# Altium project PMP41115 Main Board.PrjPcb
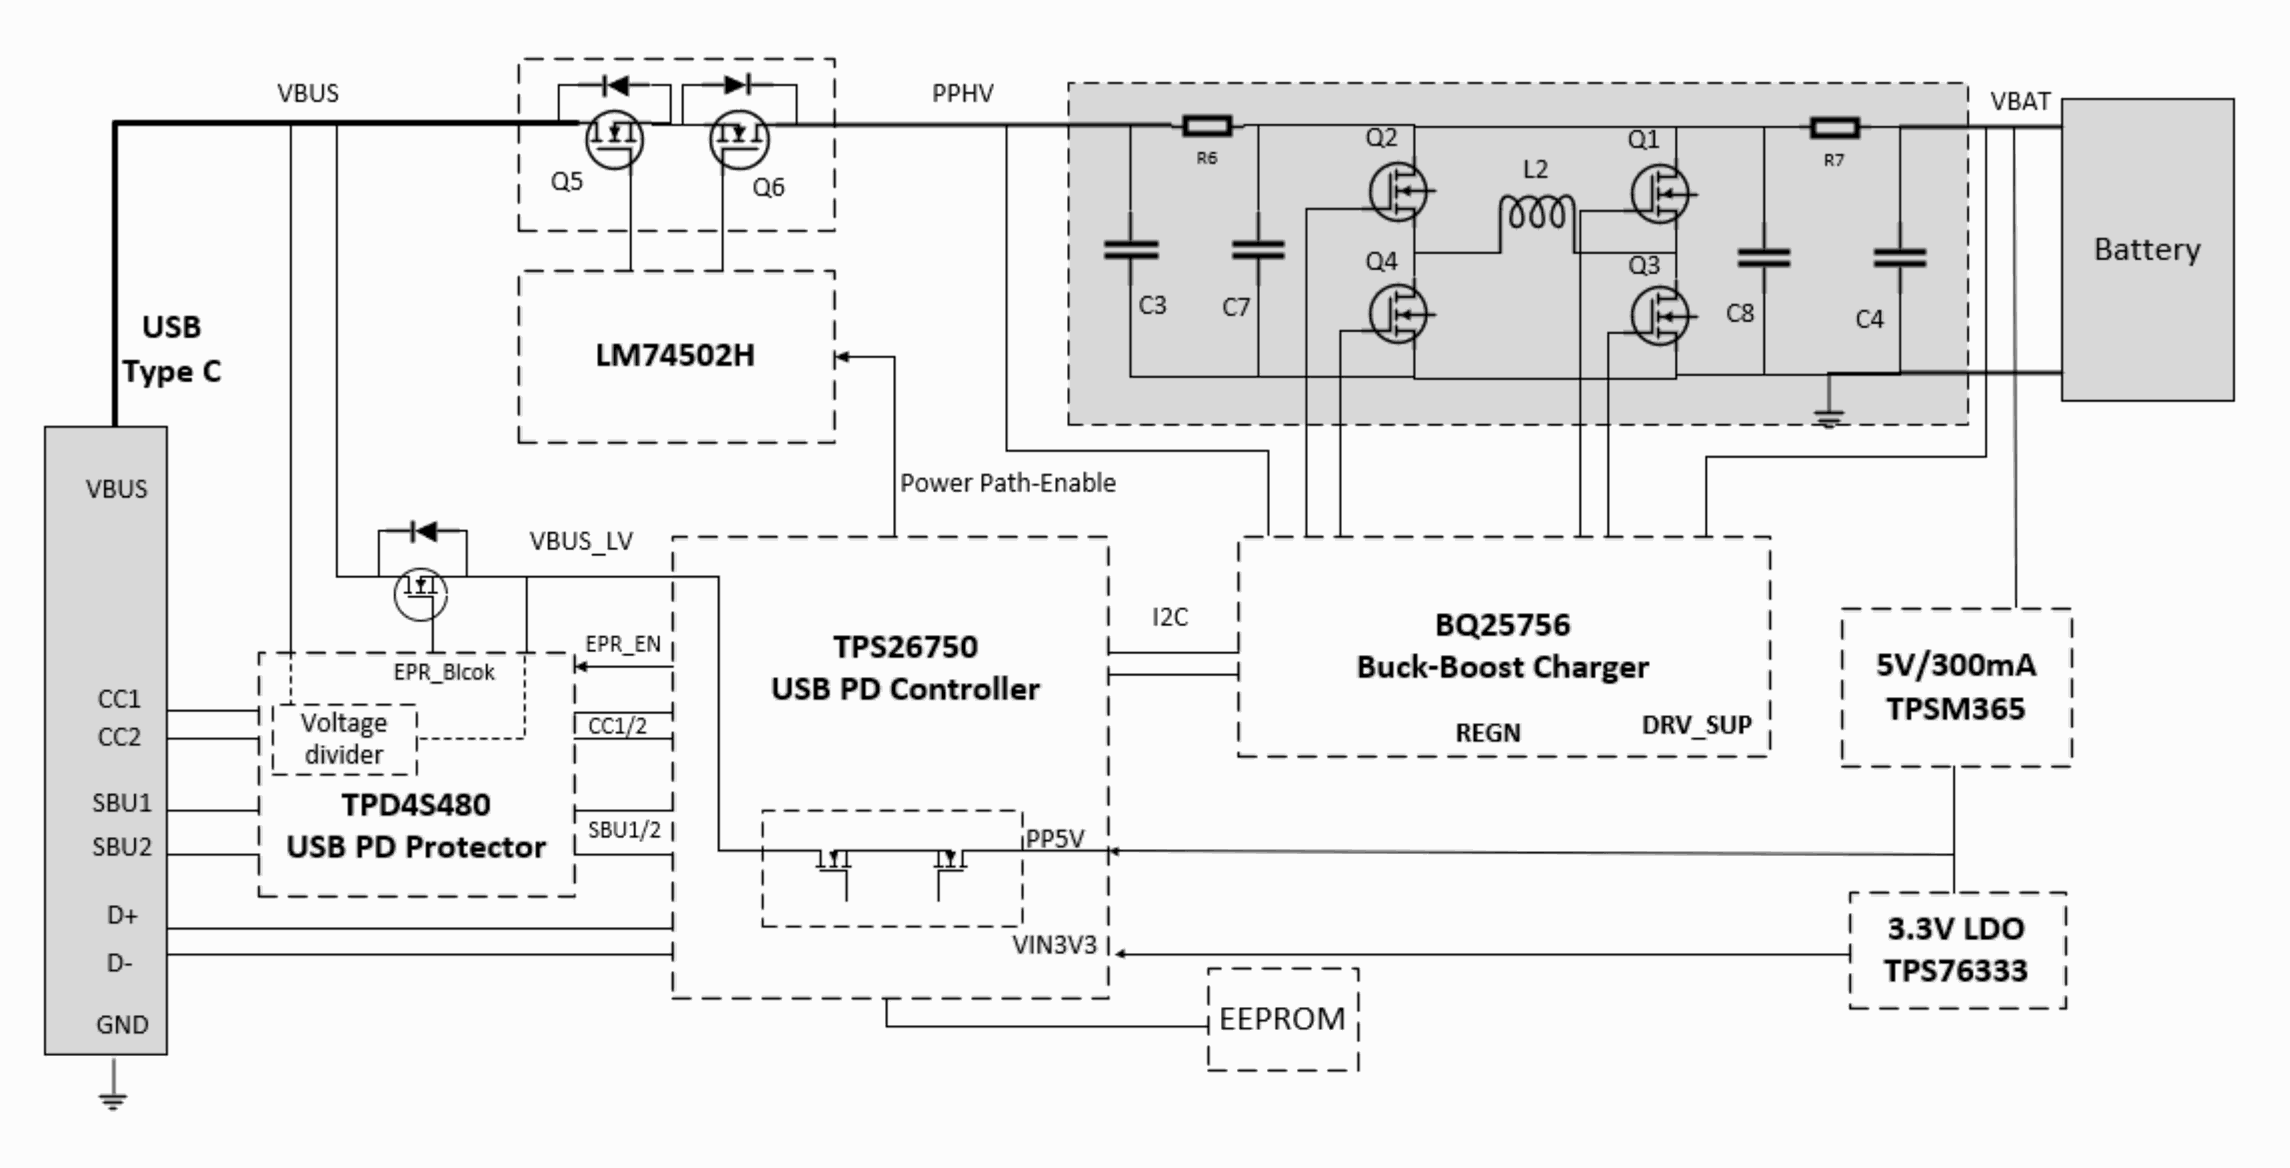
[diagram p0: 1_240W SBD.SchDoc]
CopyrightYear: 2024; PCB_Layout: Max Wang; PRJ_Customer: Public Release; PRJ_Engineer: Max Wang; PRJ_Number: PMP41115; PRJ_Title: 240W USB PD3.1 DCDC Charger; TechSupport: http://www.ti.com/support; TID: N/A
4 sheets, 168 parts. Net scope: flat (ports and power ports of the same name join across sheets).
Board file: PMP41115.PcbDoc
Sheets:
  1_240W SBD.SchDoc
  2_PD Control TPS26750.SchDoc
  4_PP5V Bias.SchDoc
  3_BQ25756 Charger.SchDoc

## Sheet 1_240W SBD.SchDoc
size A2; Date: Not shown in title block; ApprovedBy: Not shown in title block; CheckedBy: Not shown in title block; Author: Not shown in title block; CompanyName: Not shown in title block; Engineer: Not shown in title block; Organization: Not shown in title block; Address1: Not shown in title block; Address2: Not shown in title block; Address3: Not shown in title block; Address4: Not shown in title block; DocumentNumber: 1; Revision: Use project parameter SCH_Rev; SheetNumber: 1; SheetTotal: 1; PageSetup: Record=PageOptions¦CenterHorizontal=True¦CenterVertical=True¦PrintScale=0.69¦XCorrection=1.00¦YCorrection=1.00¦PrintKind=0¦BorderSize=5000000¦LeftOffset=0¦BottomOffset=0¦Orientation=2¦PaperLength=1000¦PaperWidth=1000¦Scale=100¦PaperSource=15¦PrintQuality=600¦MediaType=1¦DitherType=10¦PaperKind=Letter¦PrintScaleMode=1

## Sheet 2_PD Control TPS26750.SchDoc
size A2; Date: Not shown in title block; ApprovedBy: Not shown in title block; CheckedBy: Not shown in title block; Author: Not shown in title block; CompanyName: Not shown in title block; Engineer: Not shown in title block; Organization: Not shown in title block; Address1: Not shown in title block; Address2: Not shown in title block; Address3: Not shown in title block; Address4: Not shown in title block; DocumentNumber: 2; Revision: Use project parameter SCH_Rev; SheetNumber: 2; SheetTotal: 14; PageSetup: Record=PageOptions¦CenterHorizontal=True¦CenterVertical=True¦PrintScale=1.00¦XCorrection=1.00¦YCorrection=1.00¦PrintKind=0¦BorderSize=5000000¦LeftOffset=0¦BottomOffset=0¦Orientation=2¦PaperLength=1000¦PaperWidth=1000¦Scale=100¦PaperSource=15¦PrintQuality=600¦MediaType=1¦DitherType=10¦PaperKind=Letter¦PrintScaleMode=1
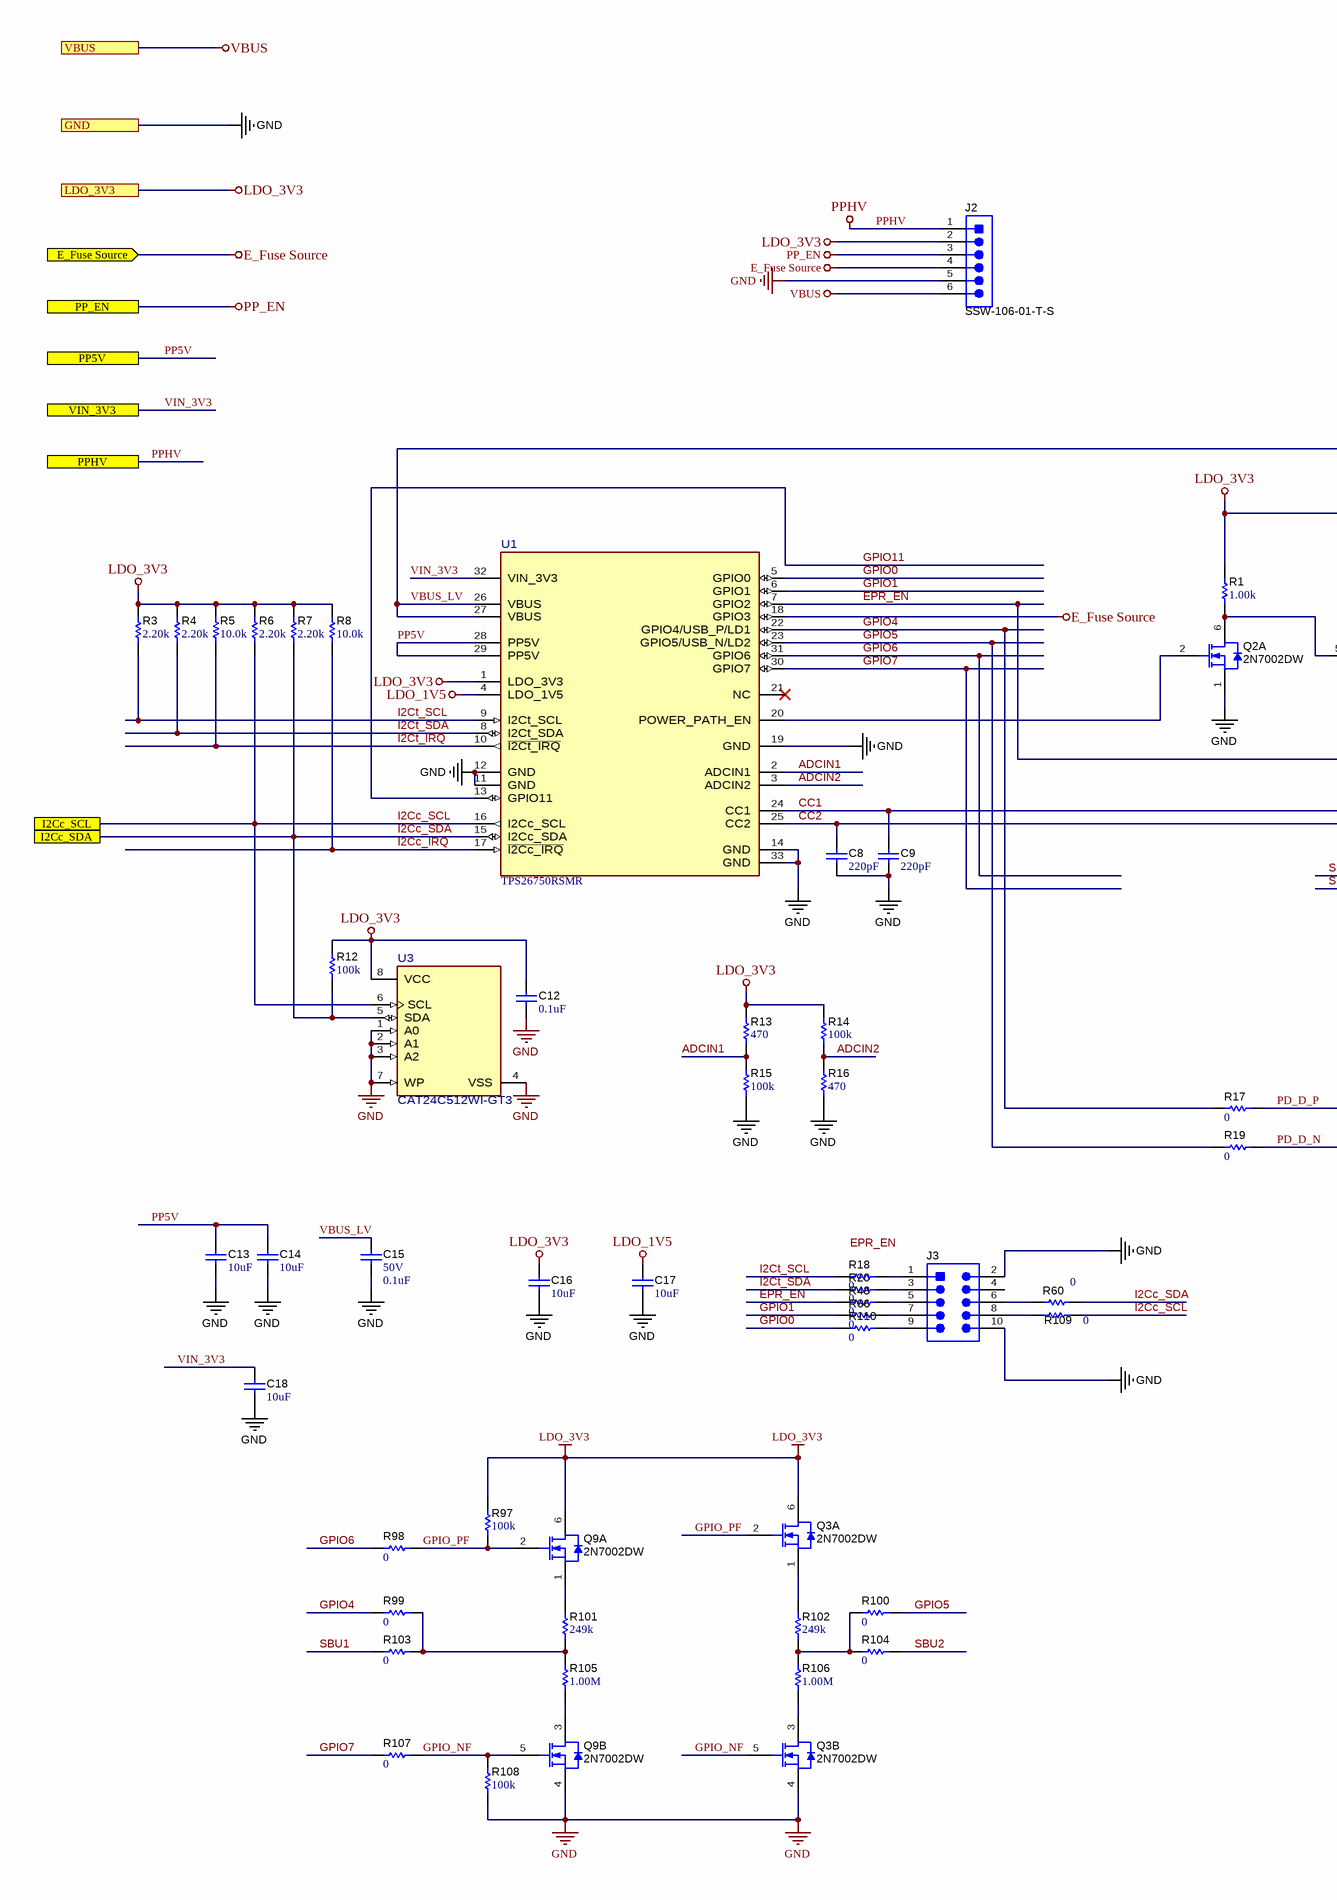
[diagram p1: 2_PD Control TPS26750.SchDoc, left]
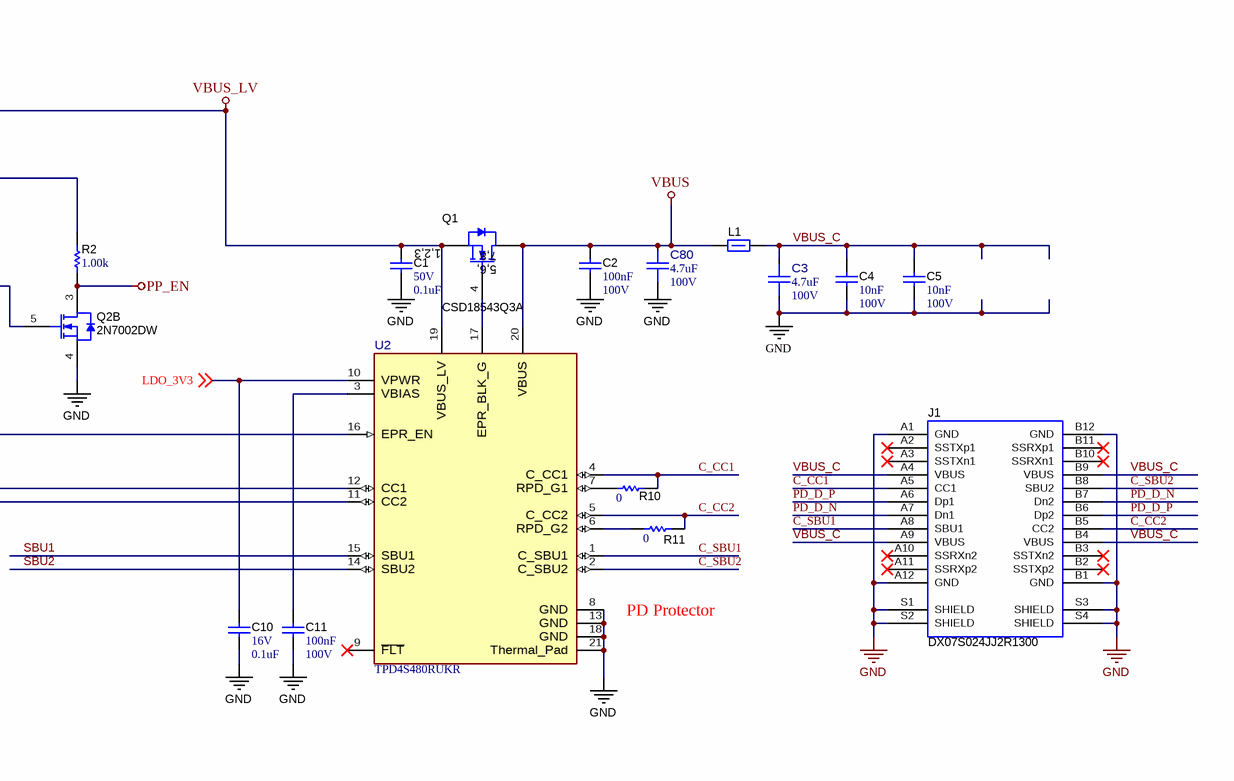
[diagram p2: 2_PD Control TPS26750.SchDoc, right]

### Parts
C1  VDC_V: 50V  ValueDisplayed: 0.1uF  [0402L]  (hidden comment: C1005X5R1H104K050BB)
C2  Cap_F: 100nF  VDC_V: 100V  [0603]  (hidden comment: GRM188R72A104KA35J)
C3  ValueDisplayed: 4.7uF  VDC_V: 100V  [FP-C2012X5R2A475K125AC_0805-MFG]  (hidden comment: C2012X5R2A475K125AC)
C4  Cap_F: 10nF  VDC_V: 100V  [0603L]  (hidden comment: C0603X103K1RACTU)
C5  Cap_F: 10nF  VDC_V: 100V  [0603L]  (hidden comment: C0603X103K1RACTU)
C8  ValueDisplayed: 220pF  [0201_033L]  (hidden comment: CGA1A2X7R1H221K030BA)
C9  ValueDisplayed: 220pF  [0201_033L]  (hidden comment: CGA1A2X7R1H221K030BA)
C10  VDC_V: 16V  ValueDisplayed: 0.1uF  [0402]  (hidden comment: 885012205037)
C11  Cap_F: 100nF  VDC_V: 100V  [0603]  (hidden comment: GRM188R72A104KA35J)
C12  ValueDisplayed: 0.1uF  [0402L]  (hidden comment: CGA2B3X7R1H104K050BB)
C13  ValueDisplayed: 10uF  [0603L]  (hidden comment: GRM188R61E106MA73D)
C14  ValueDisplayed: 10uF  [0603L]  (hidden comment: GRM188R61E106MA73D)
C15  VDC_V: 50V  ValueDisplayed: 0.1uF  [0402L]  (hidden comment: C1005X5R1H104K050BB)
C16  ValueDisplayed: 10uF  [0402_070]  (hidden comment: CL05A106MP5NUNC)
C17  ValueDisplayed: 10uF  [0402_070]  (hidden comment: CL05A106MP5NUNC)
C18  ValueDisplayed: 10uF  [0402_070]  (hidden comment: CL05A106MP5NUNC)
C80  ValueDisplayed: 4.7uF  VDC_V: 100V  [FP-C2012X5R2A475K125AC_0805-MFG]  (hidden comment: C2012X5R2A475K125AC)
J1  DX07S024JJ2R1300  [JAE_DX07S024JJ2R1300]
J2  SSW-106-01-T-S  [Samtec_SSW-106-01-x-S]
J3  PEC05DAAN  [CONN_PEC05DAAN]  (value not drawn)
L1  742792021  [0805L]  (value not drawn)
Q1  CSD18543Q3A  [DNH0008A]
Q2  2N7002DW  [SOT-363]  (parts A,B of 2)
Q3  2N7002DW  [SOT-363]  (parts A,B of 2)
Q9  2N7002DW  [SOT-363]  (parts A,B of 2)
R1  ValueDisplayed: 1.00k  [0402]  (hidden comment: ERJ-2RKF1001X)
R2  ValueDisplayed: 1.00k  [0402]  (hidden comment: ERJ-2RKF1001X)
R3  ValueDisplayed: 2.20k  [0402]  (hidden comment: RC0402FR-072K2L)
R4  ValueDisplayed: 2.20k  [0402]  (hidden comment: RC0402FR-072K2L)
R5  ValueDisplayed: 10.0k  [0402]  (hidden comment: CRCW040210K0DHEDP)
R6  ValueDisplayed: 2.20k  [0402]  (hidden comment: RC0402FR-072K2L)
R7  ValueDisplayed: 2.20k  [0402]  (hidden comment: RC0402FR-072K2L)
R8  ValueDisplayed: 10.0k  [0402]  (hidden comment: CRCW040210K0DHEDP)
R10  ValueDisplayed: 0  [0201L]  (hidden comment: CRCW02010000Z0ED)
R11  ValueDisplayed: 0  [0201L]  (hidden comment: CRCW02010000Z0ED)
R12  ValueDisplayed: 100k  [0201L]  (hidden comment: RC0201FS-7D100KL)
R13  ValueDisplayed: 470  [0603]  (hidden comment: RT0603BRD07470RL)
R14  ValueDisplayed: 100k  [0603L]  (hidden comment: RC0603FR-07100KL)
R15  ValueDisplayed: 100k  [0603L]  (hidden comment: RC0603FR-07100KL)
R16  ValueDisplayed: 470  [0603]  (hidden comment: RT0603BRD07470RL)
R17  ValueDisplayed: 0  [0201L]  (hidden comment: CRCW02010000Z0ED)
R18  ValueDisplayed: 0  [0402]  (hidden comment: RC0402JR-070RL)
R19  ValueDisplayed: 0  [0201L]  (hidden comment: CRCW02010000Z0ED)
R20  ValueDisplayed: 0  [0402]  (hidden comment: RC0402JR-070RL)
R48  ValueDisplayed: 0  [0402]  (hidden comment: RC0402JR-070RL)
R60  ValueDisplayed: 0  [0402]  (hidden comment: RC0402JR-070RL)
R66  ValueDisplayed: 0  [0402]  (hidden comment: RC0402JR-070RL)
R97  ValueDisplayed: 100k  [0402L]  (hidden comment: RC1005F104CS)
R98  ValueDisplayed: 0  [0402]  (hidden comment: RC0402JR-070RL)
R99  ValueDisplayed: 0  [0402]  (hidden comment: RC0402JR-070RL)
R100  ValueDisplayed: 0  [0402]  (hidden comment: RC0402JR-070RL)
R101  ValueDisplayed: 249k  [0603]  (hidden comment: RG1608P-2493-B-T5)
R102  ValueDisplayed: 249k  [0603]  (hidden comment: RG1608P-2493-B-T5)
R103  ValueDisplayed: 0  [0402]  (hidden comment: RC0402JR-070RL)
R104  ValueDisplayed: 0  [0402]  (hidden comment: RC0402JR-070RL)
R105  ValueDisplayed: 1.00M  [0402L]  (hidden comment: ERJ-2RKF1004X)
R106  ValueDisplayed: 1.00M  [0402L]  (hidden comment: ERJ-2RKF1004X)
R107  ValueDisplayed: 0  [0402]  (hidden comment: RC0402JR-070RL)
R108  ValueDisplayed: 100k  [0402L]  (hidden comment: RC1005F104CS)
R109  ValueDisplayed: 0  [0402]  (hidden comment: RC0402JR-070RL)
R110  ValueDisplayed: 0  [0402]  (hidden comment: RC0402JR-070RL)
U1  TPS26750RSMR  [RSM0032B-MFG]
U2  TPD4S480RUKR  [RUK0020B-MFG]
U3  CAT24C512WI-GT3  [FP-CAT24C512WI-GT3_SOIC8-IPC_C]

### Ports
E_Fuse Source (in), GND, I2Cc_SCL, I2Cc_SDA, LDO_3V3, PP5V, PP_EN, PPHV, VBUS, VIN_3V3

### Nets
E_Fuse Source: J2.4 U1.18(GPIO3) ; port E_Fuse Source
GND: C1.2 C2.2 C3.1 C4.2 C5.2 C8.2 C9.2 C10.2 C11.1 C12.2 C13.2 C14.2 C15.2 C16.1 C17.1 C18.2 C80.1 J1.A1(GND) J1.A12(GND) J1.B1(GND) J1.B12(GND) J1.S1(SHIELD) J1.S2(SHIELD) J1.S3(SHIELD) J1.S4(SHIELD) J2.5 J3.2 J3.10 Q2.1(S) Q2.4(S) Q3.4(S) Q9.4(S) R15.1 R16.1 R108.1 U1.11(GND) U1.12(GND) U1.14(GND) U1.19(GND) U1.33(GND) U2.8(GND) U2.13(GND) U2.18(GND) U2.21(Thermal_Pad) U3.1(A0) U3.2(A1) U3.3(A2) U3.4(VSS) U3.7(WP) ; port GND
LDO_1V5: C17.2 U1.4(LDO_1V5)
LDO_3V3: C10.1 C12.1 C16.2 J2.2 Q3.6(D) Q9.6(D) R1.2 R2.2 R3.2 R4.2 R5.2 R6.2 R7.2 R8.2 R12.2 R13.2 R14.2 R97.2 U1.1(LDO_3V3) U2.10(VPWR) U3.8(VCC) ; off-sheet LDO_3V3, port LDO_3V3
PP_EN: J2.3 Q2.3(D) R2.1 ; port PP_EN
PPHV: J2.1 ; port PPHV
VBUS: C2.1 C80.2 J2.6 L1.1 Q1.5(D) Q1.6(D) Q1.7(D) Q1.8(D) Q1.9(D) U2.20(VBUS) ; port VBUS
VBUS_LV: C1.1 C15.1 Q1.1(S) Q1.2(S) Q1.3(S) U1.26(VBUS) U1.27(VBUS) U2.19(VBUS_LV)
VIN_3V3: C18.1 U1.32(VIN_3V3) ; port VIN_3V3
ADCIN1: R13.1 R15.2 U1.2(ADCIN1)
ADCIN2: R14.1 R16.2 U1.3(ADCIN2)
C_CC1: J1.A5(CC1) R10.2 U2.4(C_CC1)
C_CC2: J1.B5(CC2) R11.2 U2.5(C_CC2)
C_SBU1: J1.A8(SBU1) U2.1(C_SBU1)
C_SBU2: J1.B8(SBU2) U2.2(C_SBU2)
CC1: C9.1 U1.24(CC1) U2.12(CC1)
CC2: C8.1 U1.25(CC2) U2.11(CC2)
EPR_EN: R48.1 U1.7(GPIO2) U2.16(EPR_EN)
GPIO0: R110.1 U1.5(GPIO0)
GPIO1: R66.1 U1.6(GPIO1)
GPIO4: R17.1 R99.1 U1.22(GPIO4/USB_P/LD1)
GPIO5: R19.1 R100.2 U1.23(GPIO5/USB_N/LD2)
GPIO6: R98.1 U1.31(GPIO6)
GPIO7: R107.1 U1.30(GPIO7)
GPIO11: U1.13(GPIO11)
GPIO_NF: Q3.5(G) Q9.5(G) R107.2 R108.2
GPIO_PF: Q3.2(G) Q9.2(G) R97.1 R98.2
I2Cc_SCL: R6.1 R109.2 U1.16(I2Cc_SCL) U3.6(SCL) ; port I2Cc_SCL
I2Cc_SDA: R7.1 R12.1 R60.2 U1.15(I2Cc_SDA) U3.5(SDA) ; port I2Cc_SDA
I2Ct_SCL: R3.1 R18.1 U1.9(I2Ct_SCL)
I2Ct_SDA: R4.1 R20.1 U1.8(I2Ct_SDA)
~{I2Cc_IRQ}: R8.1 U1.17(~{I2Cc_IRQ})
~{I2Ct_IRQ}: R5.1 U1.10(~{I2Ct_IRQ})
PD_D_N: J1.A7(Dn1) J1.B7(Dn2) R19.2
PD_D_P: J1.A6(Dp1) J1.B6(Dp2) R17.2
PP5V: C13.1 C14.1 U1.28(PP5V) U1.29(PP5V) ; port PP5V
SBU1: R103.1 U2.15(SBU1)
SBU2: R104.2 U2.14(SBU2)
VBUS_C: C3.2 C4.1 C5.1 J1.A4(VBUS) J1.A9(VBUS) J1.B4(VBUS) J1.B9(VBUS) L1.2
NetC11_2: C11.2 U2.3(VBIAS)
NetJ3_1: J3.1 R18.2
NetJ3_3: J3.3 R20.2
NetJ3_5: J3.5 R48.2
NetJ3_6: J3.6 R60.1
NetJ3_7: J3.7 R66.2
NetJ3_8: J3.8 R109.1
NetJ3_9: J3.9 R110.2
NetQ1_4: Q1.4(G) U2.17(EPR_BLK_G)
NetQ2_2: Q2.2(G) U1.20(POWER_PATH_EN)
NetQ2_5: Q2.5(G) Q2.6(D) R1.1
NetQ3_1: Q3.1(S) R102.2
NetQ3_3: Q3.3(D) R106.1
NetQ9_1: Q9.1(S) R101.2
NetQ9_3: Q9.3(D) R105.1
NetR10_1: R10.1 U2.7(RPD_G1)
NetR11_1: R11.1 U2.6(RPD_G2)
NetR99_2: R99.2 R101.1 R103.2 R105.2
NetR100_1: R100.1 R102.1 R104.1 R106.2

Not connected (* = marked no-connect by the designer): J1 A2(SSTXp1)* A3(SSTXn1)* A10(SSRXn2)* A11(SSRXp2)* B2(SSTXp2)* B3(SSTXn2)* B10(SSRXn1)* B11(SSRXp1)*; J3 4; U1 21(NC)*; U2 9(~{FLT})*

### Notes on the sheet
- (near U2) PD Protector
- Labels drawn without touching a wire or pin: EPR_EN

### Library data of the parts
C1 C15 = CMP-0006279-2: CAP, CERM, 0.1 uF, 50 V, +/- 10%, X5R, 0402; Manufacturer: TDK; TaMin_C: -55°C; ESR_ohm: 39.064m; Polarized: N; SizeAreaWB_mm2: 3; Value1: 0.039064 ohm; U/M: EA; Value: 0.1uF; TaMax_C: 85°C; SizeZ_mm: 0.6; SizeX_mm: 1; SizeY_mm: 0.5; Cap_Case: 0402; Cap_F: 100nF; IRMS_A: 814.669mA; AEC Category: Q200
C2 C11 = CMP-0007470-4: CAP, CERM, 0.1 uF, 100 V, +/- 10%, X7R, 0603; Manufacturer: MuRata; TaMin_C: -55°C; Polarized: N; SizeAreaWB_mm2: 4.68; Value1: Unknown; U/M: EA; Value: 0.1uF; TaMax_C: 125°C; SizeZ_mm: 1; SizeX_mm: 1.6; SizeY_mm: 0.8; SizeArea_mm2: 1.28; AEC Category: Q200
C3 C80 = CMP-0098058-1: 4.7 µF ±10% 100V Ceramic Capacitor X5R 0805 (2012 Metric); Manufacturer: TDK; AEC Qualified: No; SizeZ_mm: 1.5mm; Value: 4.7µF; TempCo: 15%
C4 C5 = CMP-0006977-4: CAP, CERM, 0.01 uF, 100 V, +/- 10%, X7R, 0603; Manufacturer: Kemet; TaMin_C: -55°C; Polarized: N; SizeAreaWB_mm2: 4.68; Value1: Unknown; U/M: EA; Value: 0.01uF; TaMax_C: 125°C; SizeZ_mm: 1; SizeX_mm: 1.6; SizeY_mm: 0.8; Cap_Case: 0603; SizeArea_mm2: 1.28; AEC Category: Q200
C8 C9 = CMP-0009652-3: CAP, CERM, 220 pF, 50 V, +/- 10%, X7R, AEC-Q200 Grade 1, 0201; Manufacturer: TDK; TaMin_C: -55°C; ESR_ohm: 11.6275; Polarized: N; SizeAreaWB_mm2: 2.08; Value1: 11.6275 ohm; U/M: EA; Value: 220pF; TaMax_C: 125°C; SizeZ_mm: 0.33; SizeX_mm: 0.6; SizeY_mm: 0.3; Cap_Case: 0201_033; Value2: 50V; SizeArea_mm2: 0.18; AEC Qualified: Y; IRMS_A: 200.785mA; AEC Grade: 1; AEC Category: Q200
C10 = CMP-0006228-1: CAP, CERM, 0.1 uF, 16 V, +/- 10%, X7R, 0402; Manufacturer: Wurth Elektronik; TaMin_C: -55°C; Polarized: N; SizeAreaWB_mm2: 3; Value1: Unknown; U/M: EA; Value: 0.1uF; TaMax_C: 125°C; SizeZ_mm: 0.6; SizeX_mm: 1; SizeY_mm: 0.5; Cap_F: 100nF; AEC Category: Q200
C12 = CMP-0006325-2: CAP, CERM, 0.1 uF, 50 V, +/- 10%, X7R, AEC-Q200 Grade 1, 0402; Manufacturer: TDK; TaMin_C: -55°C; ESR_ohm: 39.064m; Polarized: N; SizeAreaWB_mm2: 3; Value1: 0.039064 ohm; U/M: EA; Value: 0.1uF; TaMax_C: 125°C; SizeZ_mm: 0.6; SizeX_mm: 1; SizeY_mm: 0.5; Cap_Case: 0402; Value2: 50V; AEC Qualified: Y; Cap_F: 100nF; IRMS_A: 814.669mA; AEC Category: Q200
C13 C14 = CMP-0007344-5: CAP, CERM, 10 uF, 25 V, +/- 20%, X5R, 0603; Manufacturer: MuRata; TaMin_C: -55°C; Polarized: N; SizeAreaWB_mm2: 4.68; Value1: Unknown; U/M: EA; Value: 10uF; TaMax_C: 85°C; SizeZ_mm: 1; SizeX_mm: 1.6; SizeY_mm: 0.8; Cap_Case: 0603; Value2: 25V; SizeArea_mm2: 1.28; Cap_F: 10µF; AEC Category: Q200
C16-C18 = CMP-0006339-4: CAP, CERM, 10 uF, 10 V, +/- 20%, X5R, 0402; Manufacturer: Samsung Electro-Mechanics; TaMin_C: -55°C; Polarized: N; SizeAreaWB_mm2: 3; Value1: Unknown; U/M: EA; Value: 10uF; TaMax_C: 85°C; SizeZ_mm: 0.6; SizeX_mm: 1; SizeY_mm: 0.5; Cap_Case: 0402; Value2: 10V; Cap_F: 10µF; AEC Category: Q200
J1 = CMP-0085712-2: Receptacle, USB 3.1 Type C, R/A, Gold, SMT; Manufacturer: JAE Electronics; Current_A: 1.25A; Gender: Female; Voltage_V: 20V; Pitch_mm: 0.5; Row_Count: 2
J2 = CMP-0075621-1: Receptacle, 6x1, 2.54mm, Tin, TH; Manufacturer: Samtec; Pitch_mm: 2.54; Gender: Female; Cert_CSA: Y; Current_A: 5.7A; CT: False; Row_Count: 1
J3 = CMP-0054550-2: Header, 100mil, 5x2, Tin, TH; Manufacturer: Sullins Connector Solutions; Current_A: 3A; Green_Lifecycle: Active; Shrouded: N; Gender: Male; Green_REACh: Passed; Voltage_V: 1.8kV; Row_Count: 2; RowSpacing_mm: 2.54; Cert_UL: Y
L1 = CMP-0003072-1: Ferrite Bead, 22 ohm @ 100 MHz, 6 A, 0805; Manufacturer: Wurth Elektronik; Ztyp@1GHz_Ohm: 40.219; ZTyp@100MHz_Ohm: 22; SizeAreaWB_mm2: 6.75; DCR_ohm: 8m; Value1: 0.008 ohm; Value: 22 ohm; Imax_A: 6A; SizeZ_mm: 1.45; SizeX_mm: 2; SizeY_mm: 1.25; SizeArea_mm2: 2.5
Q1 = CMP-0000826-2: MOSFET, N-CH, 60 V, 35 A, DNH0008A (VSONP-8); Alternate Manufacturer: None; Manufacturer: Texas Instruments; SizeZ_mm: 0.9; ChType: N; Value2: 11.1 nC; Value1: 0.01; VdsMax_V: 60V; SizeX_mm: 3.3; SizeAreaWB_mm2: 18.49; Vgs_V: 20V; QgTyp_nC: 11.1; Value: 60V; Rdson45_ohm: 12m; SizeArea_mm2: 10.89; AEC Category: Q101; IdsMax_A: 35A; ChMode: Enhancement
Q2 Q3 Q9 = CMP-0000770-1: MOSFET, 2-CH, N-CH, 60 V, 0.115 A, SOT-363; Alternate Manufacturer: None; Manufacturer: Fairchild Semiconductor; SizeZ_mm: 1.1; ChType: N; VdsMax_V: 60V; SizeX_mm: 2.2; Vgs_V: 20V; Value: 60V; SizeArea_mm2: 4.84; AEC Category: Q101; IdsMax_A: 115mA; SizeAreaWB_mm2: 10.24; U/M: EA
R1 R2 = CMP-0026657-1: RES, 1.00 k, 1%, 0.1 W, 0402; Manufacturer: Panasonic; Power_W: 100mW; TempCo: 100 ppm/C; Value_Code: 1k00; U/M: EA; Value: 1.00k; EIA_Code: E96; Res_ohm: 1k; SizeX_mm: 1; SizeY_mm: 0.5; SizeZ_mm: 0.6; Value2: 0.1W; VDC_V: 50V; AEC Category: Q200
R3 R4 R6 R7 = CMP-0026729-1: RES, 2.20 k, 1%, 0.063 W, 0402; Manufacturer: Yageo America; Power_W: 63mW; TempCo: 100 ppm/C; Value_Code: 2k20; U/M: EA; Value: 2.20k; Res_ohm: 2.2k; SizeX_mm: 1; SizeY_mm: 0.5; SizeZ_mm: 0.6; Value2: 0.063W; AEC Qualified: N; AEC Category: Q200
R5 R8 = CMP-0026769-1: RES, 10.0 k, 0.5%, 0.063 W, 0402; Manufacturer: Vishay-Dale; Power_W: 63mW; TempCo: 50 ppm/C; Value_Code: 10k0; U/M: EA; Value: 10.0k; EIA_Code: E192; Res_ohm: 10k; SizeX_mm: 1; SizeY_mm: 0.5; SizeZ_mm: 0.6; Value2: 0.063W; VDC_V: 50V; AEC Category: Q200
R10 R11 R17 R19 = CMP-0027008-4: RES, 0, 5%, 0.05 W, 0201; Manufacturer: Vishay-Dale; Power_W: 50mW; TempCo: ppm/C; Value_Code: 0000; Value: 0; EIA_Code: E24; SizeX_mm: 0.6; SizeY_mm: 0.3; SizeZ_mm: 0.26; Value2: 0.05W; SizeArea_mm2: 0.18; AEC Qualified: N; AEC Category: Q200
R12 = CMP-0028069-1: RES, 100 k, 1%, 0.05 W, 0201; Manufacturer: Yageo America; Power_W: 50mW; TempCo: 200 ppm/C; U/M: EA; Value: 100k; EIA_Code: E96; SizeX_mm: 0.6; SizeY_mm: 0.3; SizeZ_mm: 0.26; Value2: 0.05W; SizeArea_mm2: 0.18; AEC Qualified: N; VDC_V: 25V; AEC Category: Q200
R13 R16 = CMP-0024263-1: RES, 470, 0.1%, 0.1 W, 0603; Manufacturer: Yageo America; Power_W: 100mW; TempCo: 25 ppm/C; Value_Code: 470R; U/M: EA; Value: 470; EIA_Code: E192; SizeX_mm: 1.6; SizeY_mm: 0.8; SizeZ_mm: 1; Value2: 0.1W; SizeArea_mm2: 1.28; VDC_V: 75V; AEC Category: Q200
R14 R15 = CMP-0022735-5: RES, 100 k, 1%, 0.1 W, 0603; Manufacturer: Yageo; Power_W: 100mW; TempCo: 100 ppm/C; Value: 100k; EIA_Code: E96; SizeX_mm: 1.6; SizeY_mm: 0.8; SizeZ_mm: 1; Value2: 0.1W; SizeArea_mm2: 1.28; AEC Qualified: N; VDC_V: 75V; AEC Category: Q200; SizeAreaWB_mm2: 4.68
R18 R20 R48 R60 R66 R98-R100 R103 R104 R107 R109 R110 = CMP-0027004-1: RES, 0, 5%, 0.063 W, 0402; Manufacturer: Yageo America; Power_W: 63mW; TempCo: 200 ppm/C; Value_Code: 0000; U/M: EA; Value: 0; EIA_Code: E24; SizeX_mm: 1; SizeY_mm: 0.5; SizeZ_mm: 0.6; Value2: 0.063W; VDC_V: 50V; AEC Category: Q200
R97 R108 = CMP-0026745-1: RES, 100 k, 1%, 0.063 W, 0402; Manufacturer: Samsung Electro-Mechanics; Power_W: 63mW; TempCo: 100 ppm/C; U/M: EA; Value: 100k; EIA_Code: E96; SizeX_mm: 1; SizeY_mm: 0.5; SizeZ_mm: 0.6; Value2: 0.063W; AEC Qualified: N; VDC_V: 80V; AEC Category: Q200
R101 R102 = CMP-0023490-1: RES, 249 k, 0.1%, 0.1 W, 0603; Manufacturer: Susumu Co Ltd; Power_W: 100mW; TempCo: 25 ppm/C; U/M: EA; Value: 249k; EIA_Code: E192; SizeX_mm: 1.6; SizeY_mm: 0.8; SizeZ_mm: 1; Value2: 0.1W; SizeArea_mm2: 1.28; VDC_V: 75V; AEC Category: Q200
R105 R106 = CMP-0026660-1: RES, 1.00 M, 1%, 0.1 W, 0402; Manufacturer: Panasonic; Power_W: 100mW; TempCo: 100 ppm/C; Value_Code: 1M00; U/M: EA; Value: 1.00Meg; EIA_Code: E96; Res_ohm: 1M; SizeX_mm: 1; SizeY_mm: 0.5; SizeZ_mm: 0.6; Value2: 0.1W; VDC_V: 50V; AEC Category: Q200
U1 = CMP-0121143-2: USB Type-C® and USB PD Controller with Integrated Power Switches Optimized for Power Applications; Manufacturer: Texas Instruments; SizeZ_mm: 1mm; AEC Qualified: No; Interface: I2C,USB; Max Supply Voltage: 22V; Min Supply Voltage: 3V; Nominal Supply Current: 1-3mA; Number Of Ports: 1; Standoff Height: 0mm; TaMax_C: +85°C; TaMin_C: -40°C; TJmax_C: +125°C; Usb Standard: USB 3.1; AEC Category: Q200; CompType: IC
U2 = CMP-0034161-1: USB Type-C® 48V EPR Port Protector: Short-to-VBUS Overvoltage and IEC ESD Protection; Manufacturer: Texas Instruments; SizeZ_mm: 0.8mm; AEC Qualified: No; Direction: Bidirectional; Number Of Channels: 4; Operating Supply Voltage: 3.3V; Standoff Height: 0mm; TJmax_C: +125°C
U3 = CMP-0091847-1: EEPROM Memory IC 512Kb (64K x 8) I²C 1MHz 900ns 8-SOIC; Manufacturer: ON Semi; Standoff Height: 0.1mm; AEC Qualified: No; Max Supply Voltage: 5.5V; Interface: I2C; SizeZ_mm: 1.75mm; Memory Size: 512Kbits; Min Supply Voltage: 1.8V

## Sheet 4_PP5V Bias.SchDoc
size A2; Date: Not shown in title block; ApprovedBy: Not shown in title block; CheckedBy: Not shown in title block; Author: Not shown in title block; CompanyName: Not shown in title block; Engineer: Not shown in title block; Organization: Not shown in title block; Address1: Not shown in title block; Address2: Not shown in title block; Address3: Not shown in title block; Address4: Not shown in title block; DocumentNumber: 1; Revision: Use project parameter SCH_Rev; SheetNumber: 1; SheetTotal: 1; PageSetup: Record=PageOptions¦CenterHorizontal=True¦CenterVertical=True¦PrintScale=0.69¦XCorrection=1.00¦YCorrection=1.00¦PrintKind=0¦BorderSize=5000000¦LeftOffset=0¦BottomOffset=0¦Orientation=2¦PaperLength=1000¦PaperWidth=1000¦Scale=100¦PaperSource=15¦PrintQuality=600¦MediaType=1¦DitherType=10¦PaperKind=Letter¦PrintScaleMode=1
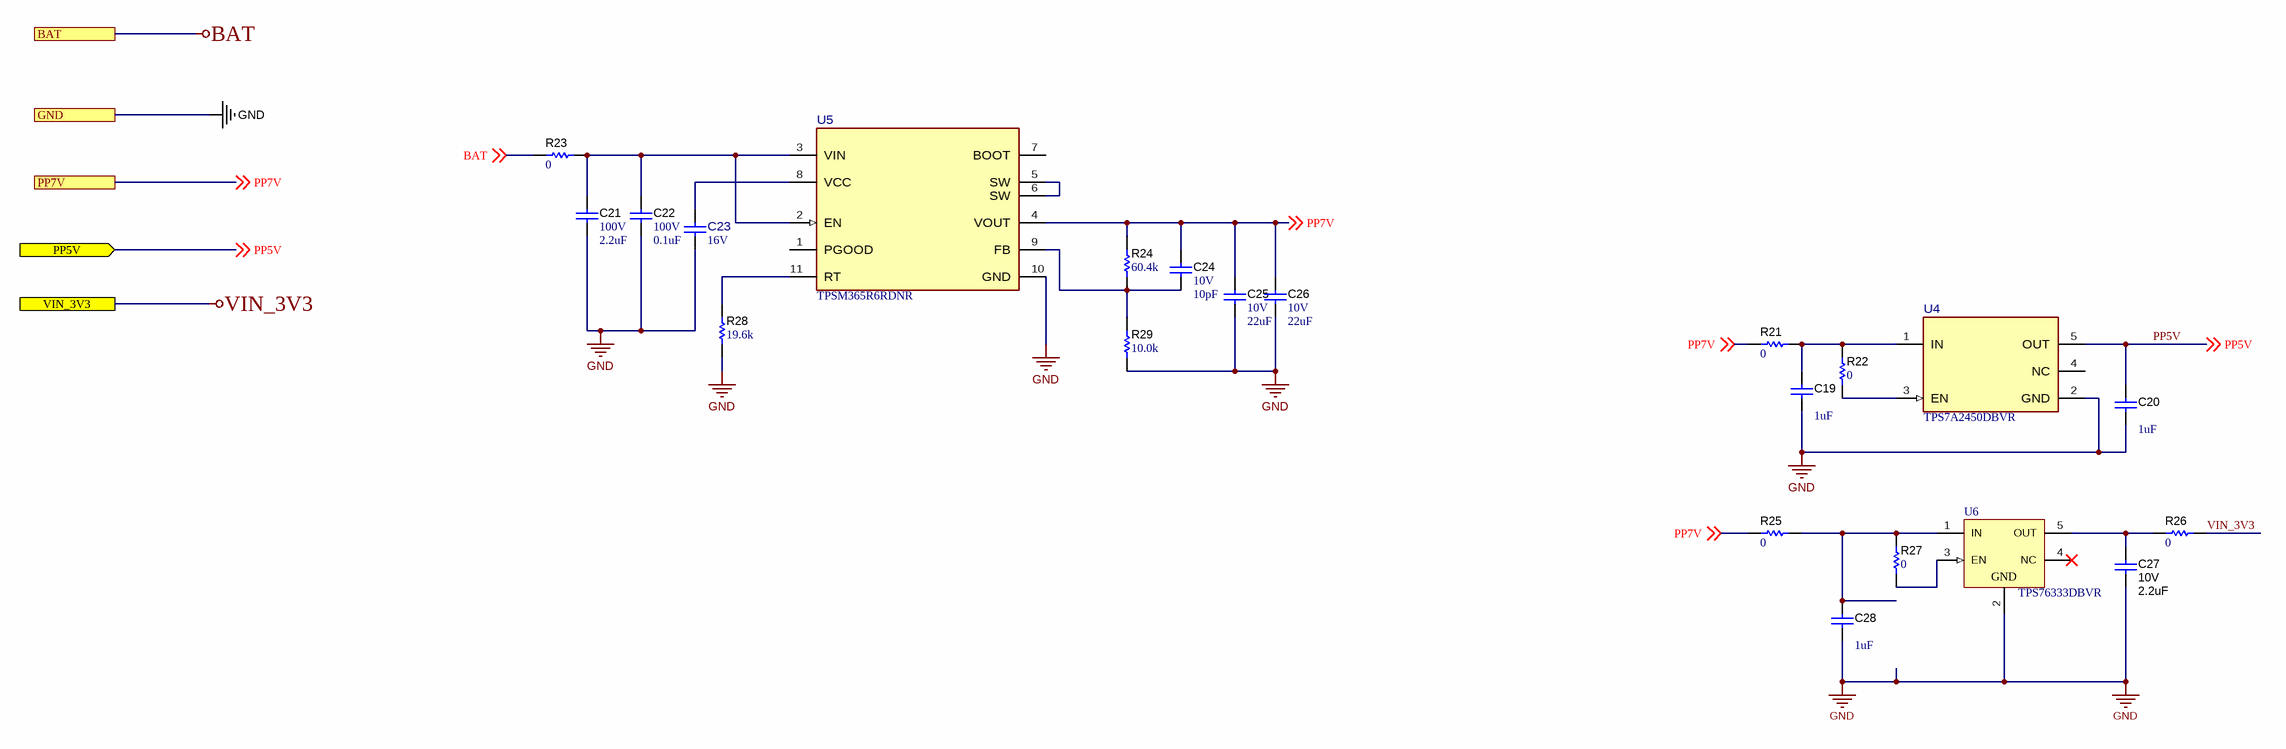
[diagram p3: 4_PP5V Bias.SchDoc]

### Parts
C19  ValueDisplayed: 1uF  [0805_HV]  (hidden comment: C2012X7S2A105K125AB)
C20  ValueDisplayed: 1uF  [0805_HV]  (hidden comment: C2012X7S2A105K125AB)
C21  VDC_V: 100V  ValueDisplayed: 2.2uF  [1206_180]  (hidden comment: C3216X7S2A225K160AB)
C22  VDC_V: 100V  ValueDisplayed: 0.1uF  [0402]  (hidden comment: GRM155R62A104KE14D)
C23  VDC_V: 16V  [FP-0402YD105KAT2A_0402-IPC_B]  (hidden comment: 0402YD105KAT2A)
C24  VDC_V: 10V  ValueDisplayed: 10pF  [0402]  (hidden comment: C0402C100C8GACTU)
C25  VDC_V: 10V  ValueDisplayed: 22uF  [0603]  (hidden comment: CL10A226MP8NUNE)
C26  VDC_V: 10V  ValueDisplayed: 22uF  [0603]  (hidden comment: CL10A226MP8NUNE)
C27  VDC_V: 10V  ValueDisplayed: 2.2uF  [0603]  (hidden comment: CGA3E3X5R1A225K080AB)
C28  ValueDisplayed: 1uF  [0805_HV]  (hidden comment: C2012X7S2A105K125AB)
R21  ValueDisplayed: 0  [0603]  (hidden comment: RC0603JR-070RL)
R22  ValueDisplayed: 0  [0402]  (hidden comment: CMP-0027004-2)
R23  ValueDisplayed: 0  [0402]  (hidden comment: CMP-0027004-2)
R24  ValueDisplayed: 60.4k  [0603]  (hidden comment: RT0603BRD0760K4L)
R25  ValueDisplayed: 0  [0603]  (hidden comment: RC0603JR-070RL)
R26  ValueDisplayed: 0  [0402]  (hidden comment: CMP-0027004-2)
R27  ValueDisplayed: 0  [0402]  (hidden comment: CMP-0027004-2)
R28  ValueDisplayed: 19.6k  [0402]  (hidden comment: CRCW040219K6FKED)
R29  ValueDisplayed: 10.0k  [0402]  (hidden comment: ERJ-2RKF1002X)
U4  TPS7A2450DBVR  [DBV0005A-MFG]
U5  TPSM365R6RDNR  [RDN0011A-MFG]
U6  TPS76333DBVR  [DBV0005A_N]

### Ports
BAT, GND, PP5V (in), PP7V, VIN_3V3

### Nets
BAT: R23.2 ; off-sheet BAT, port BAT
GND: C19.2 C20.2 C21.2 C22.2 C23.2 C25.2 C26.2 C27.2 C28.2 R28.1 R29.1 U4.2(GND) U5.10(GND) U6.2(GND) ; port GND
VIN_3V3: R26.1 ; port VIN_3V3
PP5V: C20.1 U4.5(OUT) ; off-sheet PP5V, port PP5V
PP7V: C24.1 C25.1 C26.1 R21.1 R24.2 R25.1 U5.4(VOUT) ; off-sheet PP7V, port PP7V
NetC19_1: C19.1 R21.2 R22.2 U4.1(IN)
NetC21_1: C21.1 C22.1 R23.1 U5.2(EN) U5.3(VIN)
NetC23_1: C23.1 U5.8(VCC)
NetC24_2: C24.2 R24.1 R29.2 U5.9(FB)
NetC27_1: C27.1 R26.2 U6.5(OUT)
NetC28_1: C28.1 R25.2 R27.2 U6.1(IN)
NetR22_1: R22.1 U4.3(EN)
NetR27_1: R27.1 U6.3(EN)
NetR28_2: R28.2 U5.11(RT)
NetU5_5: U5.5(SW) U5.6(SW)

Not connected (* = marked no-connect by the designer): U4 4(NC); U5 1(PGOOD) 7(BOOT); U6 4(NC)*

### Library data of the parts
C19 C20 C28 = CMP-0007891-2: CAP, CERM, 1 uF, 100 V, +/- 10%, X7S, 0805; Manufacturer: TDK; TaMin_C: -55°C; Polarized: N; SizeAreaWB_mm2: 6.75; Value1: 0.008255 ohm; U/M: EA; Value: 1uF; TaMax_C: 125°C; SizeZ_mm: 1.45; SizeX_mm: 2; SizeY_mm: 1.25; Cap_Case: 0805; Value2: 100V; SizeArea_mm2: 2.5; Cap_F: 1µF; AEC Category: Q200; ESR_ohm: 8.255m; IRMS_A: 2.2744A
C21 = CMP-0008724-2: CAP, CERM, 2.2 uF, 100 V, +/- 10%, X7S, 1206; Manufacturer: TDK; TaMin_C: -55°C; ESR_ohm: 5.718m; Polarized: N; SizeAreaWB_mm2: 10.92; Value1: 0.005718 ohm; U/M: EA; Value: 2.2uF; TaMax_C: 125°C; SizeZ_mm: 1.8; SizeX_mm: 3.2; SizeY_mm: 1.6; SizeArea_mm2: 5.12; Cap_F: 2.2µF; IRMS_A: 3.0363A; AEC Category: Q200
C22 = CMP-0006618-1: CAP, CERM, 0.1 uF, 100 V, +/- 10%, X5R, 0402; Manufacturer: MuRata; TaMin_C: -55°C; Polarized: N; SizeAreaWB_mm2: 3; Value1: Unknown; U/M: EA; Value: 0.1uF; TaMax_C: 85°C; SizeZ_mm: 0.6; SizeX_mm: 1; SizeY_mm: 0.5; Cap_F: 100nF; AEC Category: Q200
C23 = CMP-00860000-2: CAPACITOR, X5R, 0402, 16V, 1UF; Manufacturer: AVX; SizeZ_mm: 0.56mm; Value: 1µF; TempCo: 15%; Tolerance_%: 10%; AEC Qualified: No; Symbol Name: SYM-0402YD105KAT2A
C24 = CMP-0064914-1: CAP, CERM, 10 pF, 10 V,+/- 2.5%, C0G/NP0, 0402; Manufacturer: Kemet; TaMin_C: -55°C; Polarized: N; SizeAreaWB_mm2: 3; Value1: Unknown; U/M: EA; Value: 10pF; TaMax_C: 125°C; SizeZ_mm: 0.6; SizeX_mm: 1; SizeY_mm: 0.5; AEC Category: Q200
C25 C26 = CMP-0007108-2: CAP, CERM, 22 uF, 10 V, +/- 20%, X5R, 0603; Manufacturer: Samsung Electro-Mechanics; TaMin_C: -55°C; Polarized: N; SizeAreaWB_mm2: 4.68; Value1: Unknown; U/M: EA; Value: 22uF; TaMax_C: 85°C; SizeZ_mm: 1; SizeX_mm: 1.6; SizeY_mm: 0.8; SizeArea_mm2: 1.28; Cap_F: 22µF; AEC Category: Q200
C27 = CMP-0007091-5: CAP, CERM, 2.2 uF, 10 V, +/- 10%, X5R, AEC-Q200 Grade 3, 0603; Manufacturer: TDK; TaMin_C: -55°C; Polarized: N; SizeAreaWB_mm2: 4.68; Value1: Unknown; U/M: EA; Value: 2.2uF; TaMax_C: 85°C; SizeZ_mm: 1; SizeX_mm: 1.6; SizeY_mm: 0.8; SizeArea_mm2: 1.28; AEC Qualified: Y; Cap_F: 2.2µF; AEC Grade: 3; AEC Category: Q200
R21 R25 = CMP-0025885-5: RES, 0, 5%, 0.1 W, 0603; Manufacturer: Yageo; Power_W: 100mW; TempCo: 200 ppm/C; Value_Code: 0000; Value: 0; EIA_Code: E24; SizeX_mm: 1.6; SizeZ_mm: 1; Value2: 0.1W; SizeArea_mm2: 1.28; AEC Qualified: N; VDC_V: 75V; AEC Category: Q200; SizeY_mm: 0.8; SizeAreaWB_mm2: 4.68
R22 R23 R26 R27 = CMP-0027004-2: RES, 0, 5%, 0.063 W, 0402; PartNumber: RC0402JR-070RL; Manufacturer: Yageo America; Value: 0; Value_Code: 0000; Power_W: 63mW; Value2: 0.063W; VDC_V: 50V; TempCo: 200 ppm/C; SizeArea_mm2: 0.5; SizeX_mm: 1; SizeZ_mm: 0.6; EIA_Code: E24; U/M: EA; AEC Category: Q200
R24 = CMP-0024382-2: RES, 60.4 k, 0.1%, 0.1 W, 0603; Manufacturer: Yageo America; Power_W: 100mW; TempCo: 25 ppm/C; Value_Code: 60k4; U/M: EA; Value: 60.4k; EIA_Code: E192; SizeX_mm: 1.6; SizeY_mm: 0.8; SizeZ_mm: 1; Value2: 0.1W; SizeArea_mm2: 1.28; VDC_V: 75V; AEC Category: Q200
R28 = CMP-0026068-2: RES, 19.6 k, 1%, 0.063 W, 0402; Manufacturer: Vishay-Dale; Power_W: 63mW; TempCo: 100 ppm/C; Value_Code: 19k6; U/M: EA; Value: 19.6k; EIA_Code: E96; SizeX_mm: 1; SizeY_mm: 0.5; SizeZ_mm: 0.6; Value2: 0.063W; VDC_V: 50V; AEC Category: Q200
R29 = CMP-0026658-1: RES, 10.0 k, 1%, 0.1 W, 0402; Manufacturer: Panasonic; Power_W: 100mW; TempCo: 100 ppm/C; Value_Code: 10k0; U/M: EA; Value: 10.0k; EIA_Code: E96; Res_ohm: 10k; SizeX_mm: 1; SizeY_mm: 0.5; SizeZ_mm: 0.6; Value2: 0.1W; VDC_V: 50V; AEC Category: Q200
U4 = CMP-0096923-1: Linear Voltage Regulator IC  1 Output  200mA SOT-23-5; Manufacturer: Texas Instruments; AEC Qualified: No; Standoff Height: 0mm; Accuracy Percentage: 2%; SizeZ_mm: 1.45mm; Number Of Outputs: 1; TJmax_C: +125°C; Max Supply Voltage: 18V; Output Type: Fixed; Nominal Supply Current: 2-15uA; Dropout Voltage: 160mV; Output Voltage: 5V; Min Supply Voltage: 2.4V
U5 = CMP-0096774-1: 3 V to 65 V Input, 1 V to 13 V Output, 600-mA Synchronous Buck Converter Power Module in a HotRod™ QFN Package; Manufacturer: Texas Instruments; Min Supply Voltage: 3.6V; Output Voltage: 1-13V; Max Duty Cycle: 98%; Output Type: AdjustableProgrammable; SizeZ_mm: 2.1mm; Switching Frequency: 200-2200kHz; AEC Qualified: No; Nominal Supply Current: 17-18uA; Standoff Height: 0mm; Number Of Outputs: 1; Max Supply Voltage: 65V; TJmax_C: +125°C
U6 = CMP-0035539-1: Single Output LDO, 150 mA, Fixed 3.3 V Output, 2.7 to 10 V Input, with Low IQ, 5-pin SOT-23 (DBV), -40 to 125 degC, Green (RoHS & no Sb/Br); Manufacturer: Texas Instruments; Fixed Output Options(V): 3.3; SubFamily: Single Channel LDO; Vdo(Typ)(mV): 300; Accuracy(%): 3; Vin(Max)(V): 10; Iq(Typ)(mA): 0.08; Vin(Min)(V): 2.7; Iout(Max)(A): 0.15

## Sheet 3_BQ25756 Charger.SchDoc
size A2; Date: Not shown in title block; ApprovedBy: Not shown in title block; CheckedBy: Not shown in title block; Author: Not shown in title block; CompanyName: Not shown in title block; Engineer: Not shown in title block; Organization: Not shown in title block; Address1: Not shown in title block; Address2: Not shown in title block; Address3: Not shown in title block; Address4: Not shown in title block; DocumentNumber: 1; Revision: Use project parameter SCH_Rev; SheetNumber: 3; SheetTotal: 4; PageSetup: Record=PageOptions¦CenterHorizontal=True¦CenterVertical=True¦PrintScale=0.69¦XCorrection=1.00¦YCorrection=1.00¦PrintKind=0¦BorderSize=5000000¦LeftOffset=0¦BottomOffset=0¦Orientation=2¦PaperLength=1000¦PaperWidth=1000¦Scale=100¦PaperSource=15¦PrintQuality=600¦MediaType=1¦DitherType=10¦PaperKind=Letter¦PrintScaleMode=1
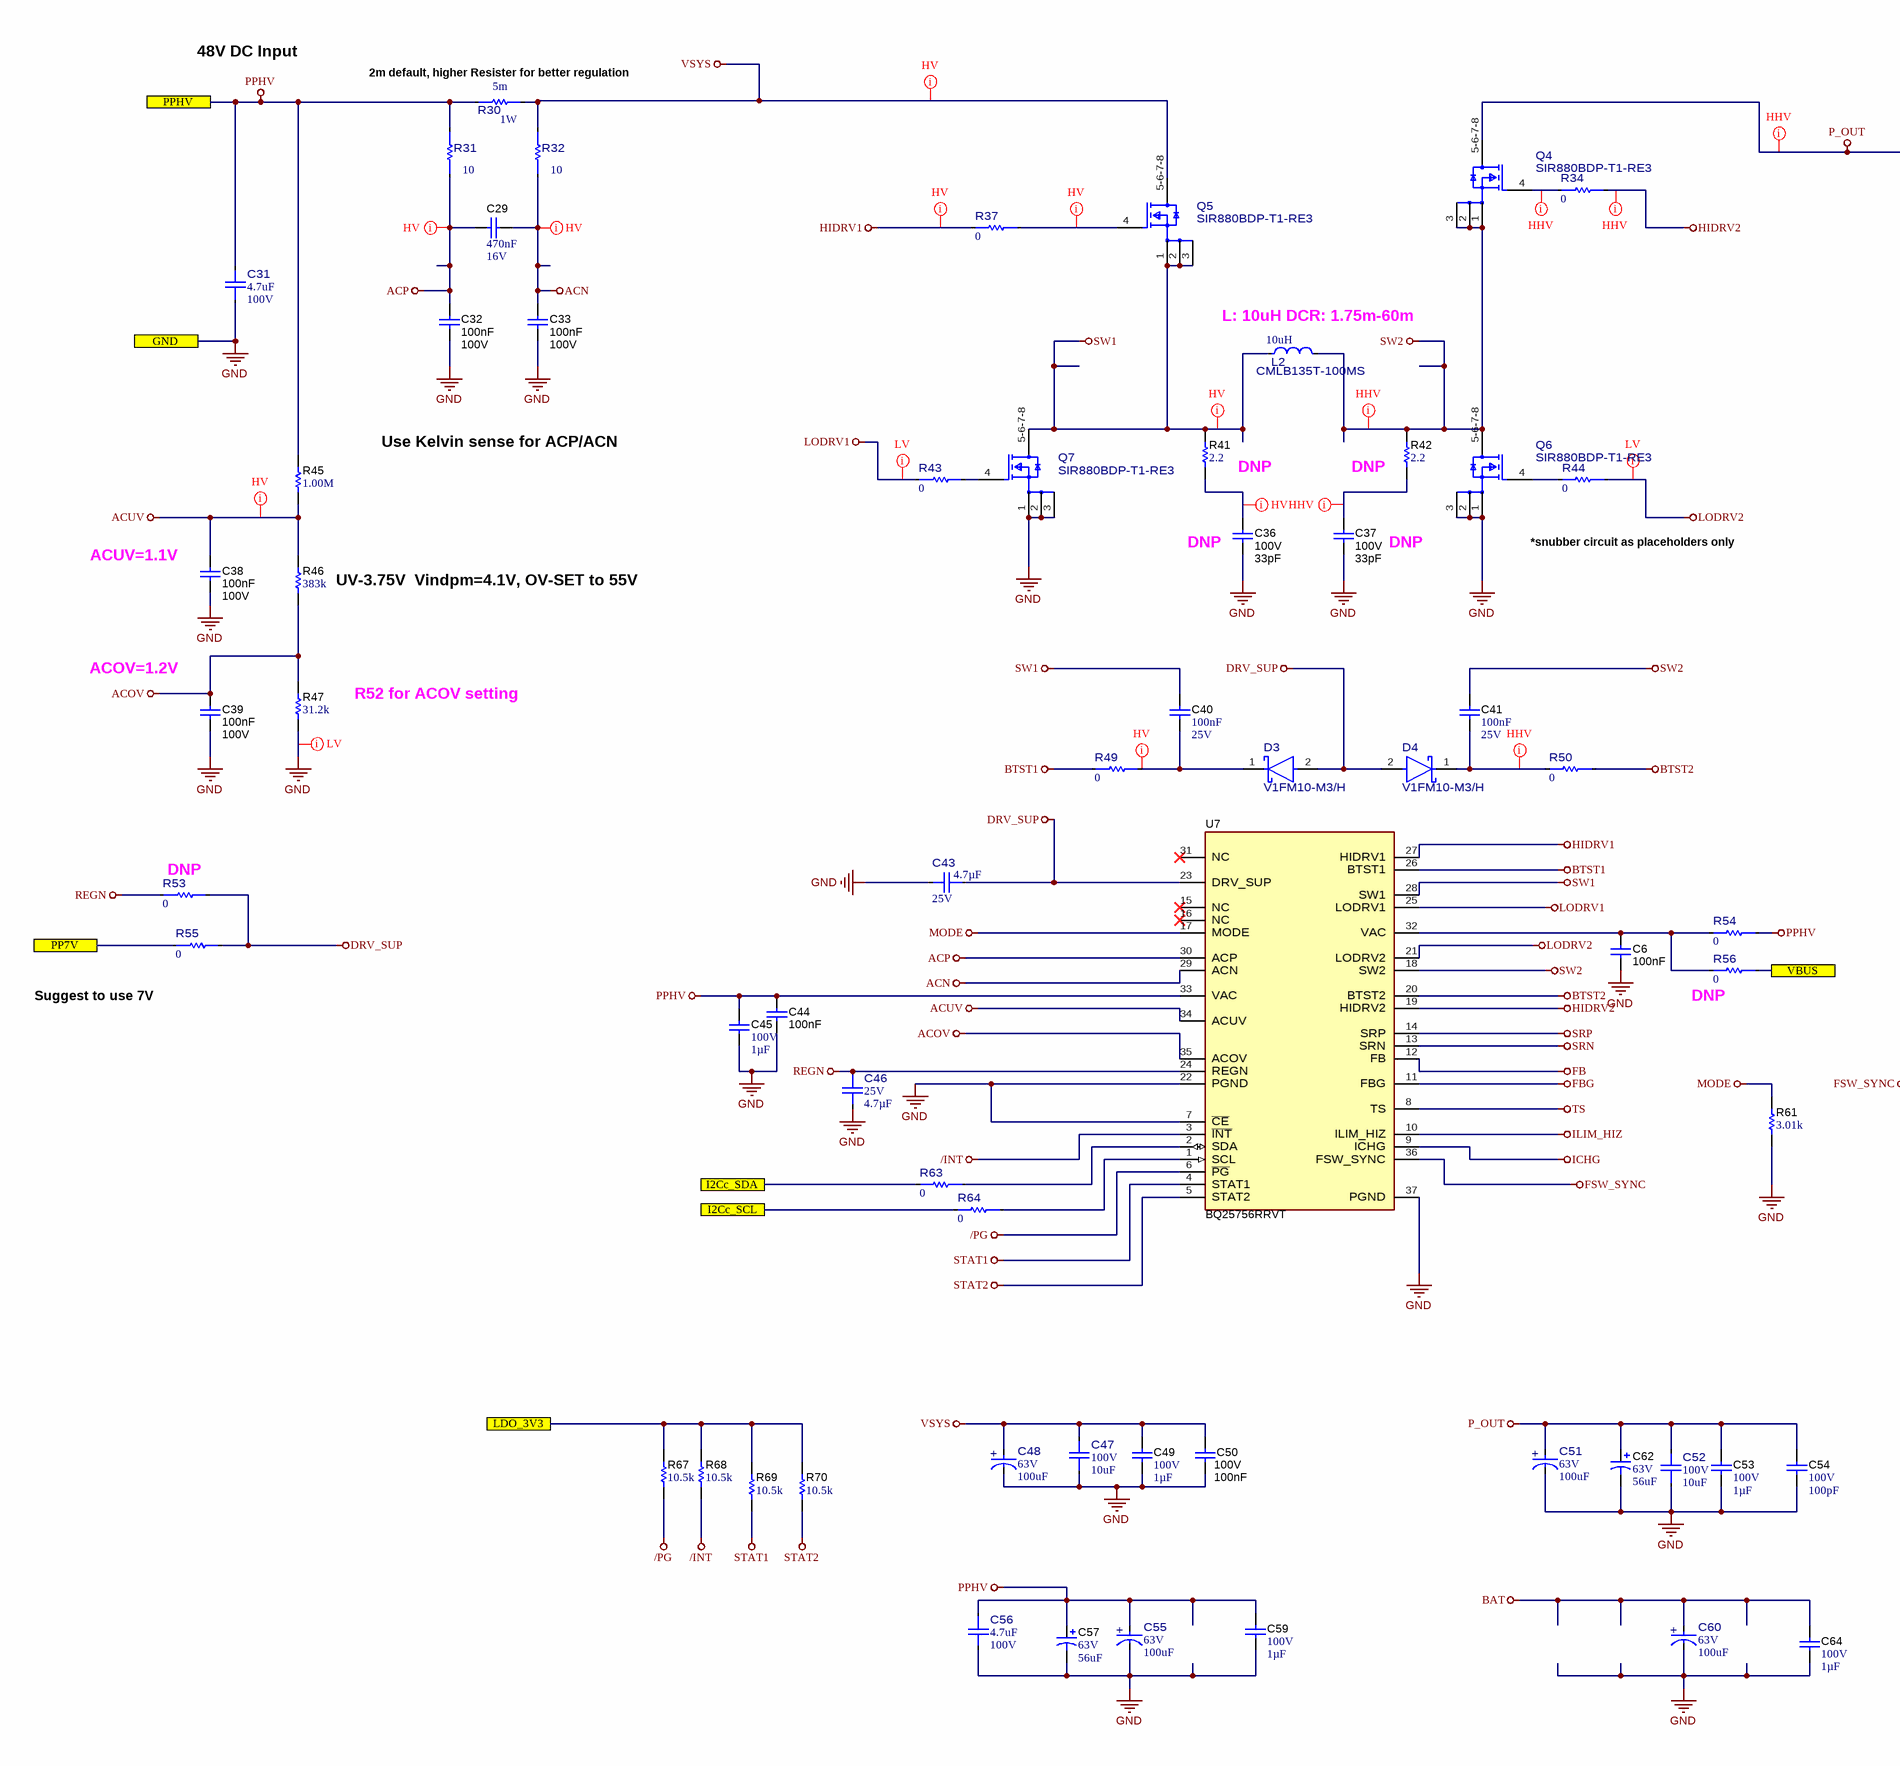
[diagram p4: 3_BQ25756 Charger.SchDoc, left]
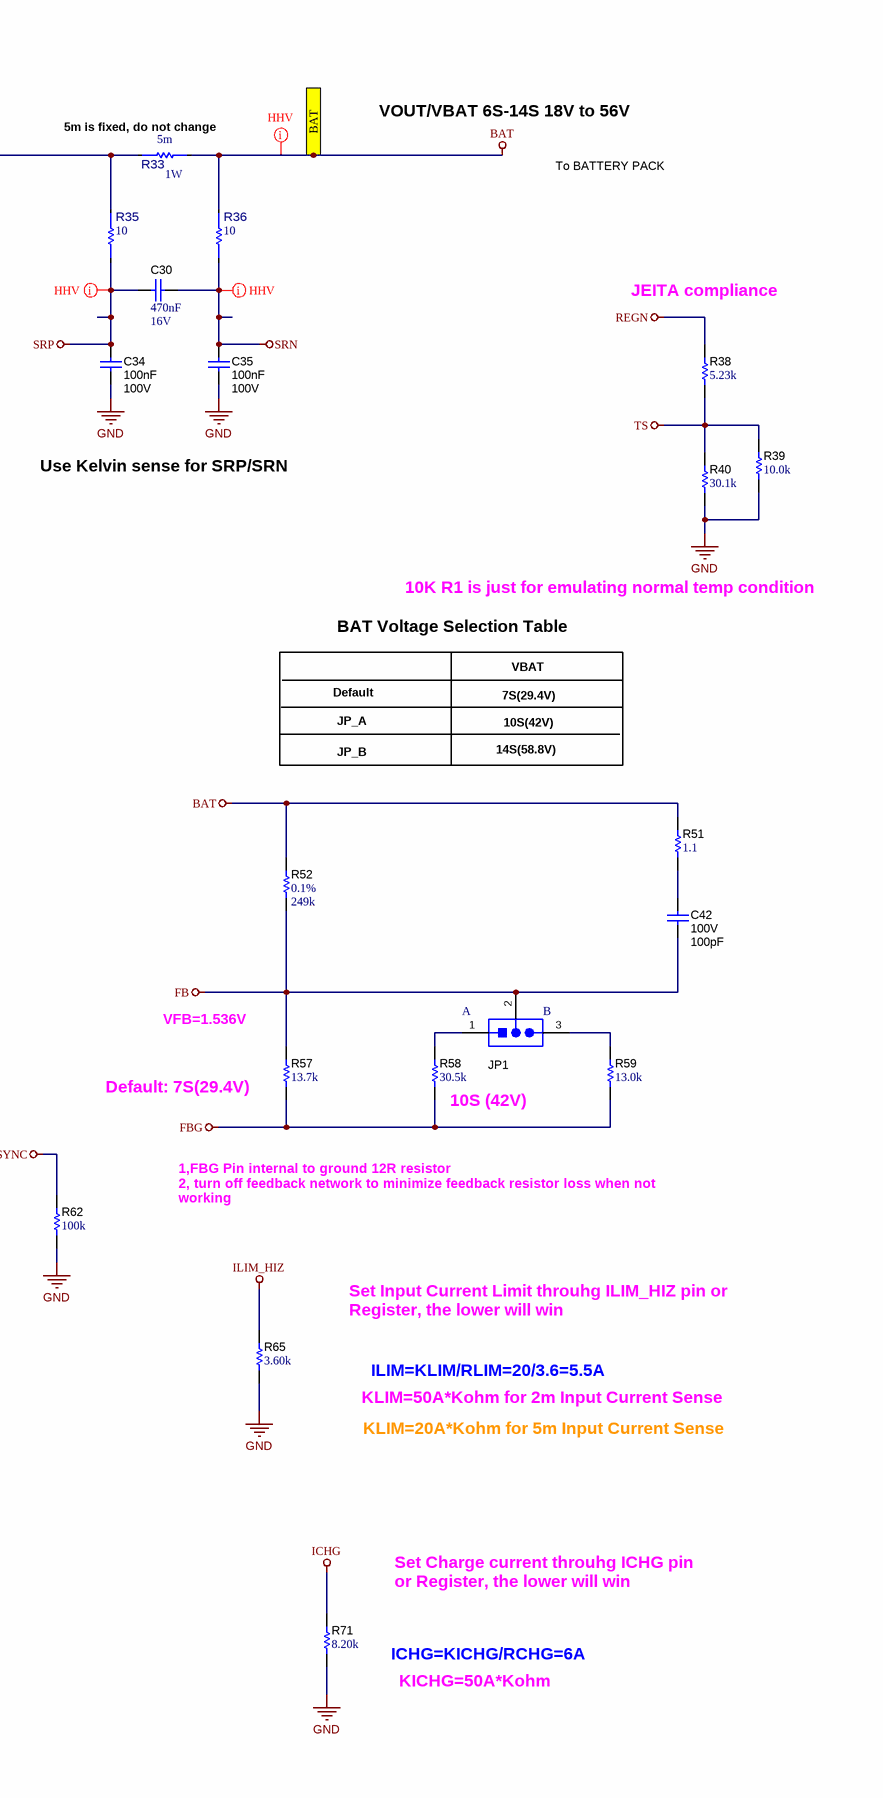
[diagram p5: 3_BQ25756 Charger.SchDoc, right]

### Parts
C6  Cap_F: 100nF  [0603_HV]  (hidden comment: HMK107B7104KAHT)
C29  Cap_F: 470nF  VDC_V: 16V  [0603]  (hidden comment: C0603C474K4RACTU)
C30  Cap_F: 470nF  VDC_V: 16V  [0603]  (hidden comment: C0603C474K4RACTU)
C31  ValueDisplayed: 4.7uF  VDC_V: 100V  [FP-GCJ32DC72A475KE01L_1210-MFG]  (hidden comment: GCJ32DC72A475KE01L)
C32  Cap_F: 100nF  VDC_V: 100V  [0603_HV]  (hidden comment: HMK107B7104KAHT)
C33  Cap_F: 100nF  VDC_V: 100V  [0603_HV]  (hidden comment: HMK107B7104KAHT)
C34  Cap_F: 100nF  VDC_V: 100V  [0603_HV]  (hidden comment: HMK107B7104KAHT)
C35  Cap_F: 100nF  VDC_V: 100V  [0603_HV]  (hidden comment: HMK107B7104KAHT)
C36  VDC_V: 100V  ValueDisplayed: 33pF  [0603_HV]  (hidden comment: 06031A330JAT2A)
C37  VDC_V: 100V  ValueDisplayed: 33pF  [0603_HV]  (hidden comment: 06031A330JAT2A)
C38  Cap_F: 100nF  VDC_V: 100V  [0603_HV]  (hidden comment: HMK107B7104KAHT)
C39  Cap_F: 100nF  VDC_V: 100V  [0603_HV]  (hidden comment: HMK107B7104KAHT)
C40  Cap_F: 100nF  VDC_V: 25V  [0603_HV]  (hidden comment: 06033C104KAT2A)
C41  Cap_F: 100nF  VDC_V: 25V  [0603_HV]  (hidden comment: 06033C104KAT2A)
C42  VDC_V: 100V  ValueDisplayed: 100pF  [0603_HV]  (hidden comment: GCM1885C2A101JA16D)
C43  VDC_V: 25V  Cap_F: 4.7µF  [FP-CGA4J1X7R1E475K125AE_0805-MFG]  (hidden comment: CGA4J1X7R1E475K125AE)
C44  Cap_F: 100nF  [0603_HV]  (hidden comment: HMK107B7104KAHT)
C45  VDC_V: 100V  Cap_F: 1µF  [0805_150]  (hidden comment: 08051C105K4Z2A)
C46  VDC_V: 25V  Cap_F: 4.7µF  [FP-CGA4J1X7R1E475K125AE_0805-MFG]  (hidden comment: CGA4J1X7R1E475K125AE)
C47  VDC_V: 100V  ValueDisplayed: 10uF  [FP-C3225X7R2A106K250AC_1210-MFG]  (hidden comment: C3225X7R2A106K250AC)
C48  VDC_V: 63V  ValueDisplayed: 100uF  [FP-PCR1J101MCL1GS_SMD_RADIAL-MFG]  (hidden comment: PCR1J101MCL1GS)
C49  VDC_V: 100V  Cap_F: 1µF  [0805_150]  (hidden comment: 08051C105K4Z2A)
C50  Cap_F: 100nF  VDC_V: 100V  [0603L]  (hidden comment: HMK107B7104KAHT)
C51  VDC_V: 63V  ValueDisplayed: 100uF  [FP-PCR1J101MCL1GS_SMD_RADIAL-MFG]  (hidden comment: PCR1J101MCL1GS)
C52  VDC_V: 100V  ValueDisplayed: 10uF  [FP-C3225X7R2A106K250AC_1210-MFG]  (hidden comment: C3225X7R2A106K250AC)
C53  VDC_V: 100V  Cap_F: 1µF  [0805_150]  (hidden comment: 08051C105K4Z2A)
C54  VDC_V: 100V  ValueDisplayed: 100pF  [0603]  (hidden comment: CGA3E2C0G2A101J080AA)
C55  VDC_V: 63V  ValueDisplayed: 100uF  [FP-PCR1J101MCL1GS_SMD_RADIAL-MFG]  (hidden comment: PCR1J101MCL1GS)
C56  ValueDisplayed: 4.7uF  VDC_V: 100V  [FP-GCJ32DC72A475KE01L_1210-MFG]  (hidden comment: GCJ32DC72A475KE01L)
C57  VDC_V: 63V  ValueDisplayed: 56uF  [SM_RADIAL_10BMM]  (hidden comment: EEHZC1J560P)
C59  VDC_V: 100V  Cap_F: 1µF  [0805_150]  (hidden comment: 08051C105K4Z2A)
C60  VDC_V: 63V  ValueDisplayed: 100uF  [FP-PCR1J101MCL1GS_SMD_RADIAL-MFG]  (hidden comment: PCR1J101MCL1GS)
C62  VDC_V: 63V  ValueDisplayed: 56uF  [SM_RADIAL_10BMM]  (hidden comment: EEHZC1J560P)
C64  VDC_V: 100V  Cap_F: 1µF  [0805_150]  (hidden comment: 08051C105K4Z2A)
D3  V1FM10-M3/H  [FP-V1FM10-M3-H_DO-219AB-MFG]
D4  V1FM10-M3/H  [FP-V1FM10-M3-H_DO-219AB-MFG]
JP1  PEC03SAAN  [CONN_PEC03SAAN]  (value not drawn)
L2  CMLB135T-100MS  value 10uH  [FP-CMLB135T-100MS_SMT2_13MM45_12Mm6-MFG]
Q4  SIR880BDP-T1-RE3  [FP-SIR880BDP-T1-RE3_SO-8-MFG]
Q5  SIR880BDP-T1-RE3  [FP-SIR880BDP-T1-RE3_SO-8-MFG]
Q6  SIR880BDP-T1-RE3  [FP-SIR880BDP-T1-RE3_SO-8-MFG]
Q7  SIR880BDP-T1-RE3  [FP-SIR880BDP-T1-RE3_SO-8-MFG]
R30  Res_ohm: 5m  Power_W: 1W  [FP-WSL25125L000FEA_2512-MFG]  (hidden comment: WSL25125L000FEA)
R31  value 10  [FP-CRCW060310R0FKEB_0603-MFG]  (hidden comment: CRCW060310R0FKEB)
R32  value 10  [FP-CRCW060310R0FKEB_0603-MFG]  (hidden comment: CRCW060310R0FKEB)
R33  Res_ohm: 5m  Power_W: 1W  [FP-WSL25125L000FEA_2512-MFG]  (hidden comment: WSL25125L000FEA)
R34  value 0  [FP-CRCW06031R50FKEAHP_0603-MFG]  (hidden comment: CRCW06030000Z0EA)
R35  value 10  [FP-CRCW060310R0FKEB_0603-MFG]  (hidden comment: CRCW060310R0FKEB)
R36  value 10  [FP-CRCW060310R0FKEB_0603-MFG]  (hidden comment: CRCW060310R0FKEB)
R37  value 0  [FP-CRCW06031R50FKEAHP_0603-MFG]  (hidden comment: CRCW06030000Z0EA)
R38  ValueDisplayed: 5.23k  [0603]  (hidden comment: RC0603FR-075K23L)
R39  ValueDisplayed: 10.0k  [0603]  (hidden comment: ERJ-3EKF1002V)
R40  ValueDisplayed: 30.1k  [0603]  (hidden comment: RC0603FR-0730K1L)
R41  ValueDisplayed: 2.2  [0805_HV]  (hidden comment: RC0805JR-072R2L)
R42  ValueDisplayed: 2.2  [0805_HV]  (hidden comment: RC0805JR-072R2L)
R43  value 0  [FP-CRCW06031R50FKEAHP_0603-MFG]  (hidden comment: CRCW06030000Z0EA)
R44  value 0  [FP-CRCW06031R50FKEAHP_0603-MFG]  (hidden comment: CRCW06030000Z0EA)
R45  ValueDisplayed: 1.00M  [0805_HV]  (hidden comment: CRCW08051M00FKEAC)
R46  ValueDisplayed: 383k  [0603]  (hidden comment: RT0603BRD07383KL)
R47  ValueDisplayed: 31.2k  [0603]  (hidden comment: RT0603BRD0731K2L)
R49  value 0  [FP-CRCW06031R50FKEAHP_0603-MFG]  (hidden comment: CRCW06030000Z0EA)
R50  value 0  [FP-CRCW06031R50FKEAHP_0603-MFG]  (hidden comment: CRCW06030000Z0EA)
R51  ValueDisplayed: 1.1  [0603]  (hidden comment: CRCW06031R10JNEA)
R52  Value1: 0.1%  ValueDisplayed: 249k  [0805_HV]  (hidden comment: ERJ-PB6B2493V)
R53  value 0  [FP-CRCW06031R50FKEAHP_0603-MFG]  (hidden comment: CRCW06030000Z0EA)
R54  value 0  [FP-CRCW06031R50FKEAHP_0603-MFG]  (hidden comment: CRCW06030000Z0EA)
R55  value 0  [FP-CRCW06031R50FKEAHP_0603-MFG]  (hidden comment: CRCW06030000Z0EA)
R56  value 0  [FP-CRCW06031R50FKEAHP_0603-MFG]  (hidden comment: CRCW06030000Z0EA)
R57  ValueDisplayed: 13.7k  [0603]  (hidden comment: RT0603BRD0713K7L)
R58  ValueDisplayed: 30.5k  [0603]  (hidden comment: RT0603BRD0730K5L)
R59  ValueDisplayed: 13.0k  [0603]  (hidden comment: RT0603BRD0713KL)
R61  ValueDisplayed: 3.01k  [0603]  (hidden comment: CRCW06033K01FKEA)
R62  ValueDisplayed: 100k  [0603]  (hidden comment: RC0603FR-07100KL)
R63  value 0  [FP-CRCW080510R0JNEAHP_0805-MFG]  (hidden comment: CRCW08050000Z0EA)
R64  value 0  [FP-CRCW080510R0JNEAHP_0805-MFG]  (hidden comment: CRCW08050000Z0EA)
R65  ValueDisplayed: 3.60k  [0603]  (hidden comment: RC0603FR-073K6L)
R67  ValueDisplayed: 10.5k  [0402]  (hidden comment: RC0402FR-0710K5L)
R68  ValueDisplayed: 10.5k  [0402]  (hidden comment: RC0402FR-0710K5L)
R69  ValueDisplayed: 10.5k  [0402]  (hidden comment: RC0402FR-0710K5L)
R70  ValueDisplayed: 10.5k  [0402]  (hidden comment: RC0402FR-0710K5L)
R71  ValueDisplayed: 8.20k  [0603]  (hidden comment: RG1608P-822-B-T5)
U7  BQ25756RRVT  [RRV0036A-MFG]

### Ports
BAT, GND, I2Cc_SCL, I2Cc_SDA, LDO_3V3, PP7V, PPHV, VBUS

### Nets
/INT: R68.1 U7.3(~{INT})
/PG: R67.1 U7.6(~{PG})
ACN: C29.2 C33.1 R32.1 U7.29(ACN)
ACOV: C39.1 R46.1 R47.2 U7.35(ACOV)
ACP: C29.1 C32.1 R31.1 U7.30(ACP)
ACUV: C38.1 R45.1 R46.2 U7.34(ACUV)
BAT: C60.2(ANODE) C64.1 R33.2 R36.1 R51.2 R52.2 ; port BAT
BTST1: R49.1 U7.26(BTST1)
BTST2: R50.1 U7.20(BTST2)
DRV_SUP: C43.1 D3.2(ANODE) D4.2(ANODE) R53.2 R55.2 U7.23(DRV_SUP)
FB: C42.2 JP1.2 R52.1 R57.2 U7.12(FB)
FBG: R57.1 R58.1 R59.1 U7.11(FBG)
FSW_SYNC: R62.2 U7.36(FSW_SYNC)
GND: C6.1 C31.1 C32.2 C33.2 C34.2 C35.2 C36.2 C37.2 C38.2 C39.2 C43.2 C44.1 C45.2 C46.2 C47.1 C48.1(CATHODE) C49.2 C50.2 C51.1(CATHODE) C52.1 C53.2 C54.2 C55.1(CATHODE) C56.2 C57.2(-) C59.2 C60.1(CATHODE) C62.2(-) C64.2 Q6.1(S) Q6.2(S) Q6.3(S) Q7.1(S) Q7.2(S) Q7.3(S) R39.1 R40.1 R47.1 R61.1 R62.1 R65.1 R71.1 U7.7(~{CE}) U7.22(PGND) U7.37(PGND) ; port GND
HIDRV1: R37.2 U7.27(HIDRV1)
HIDRV2: R34.2 U7.19(HIDRV2)
ICHG: R71.2 U7.9(ICHG)
ILIM_HIZ: R65.2 U7.10(ILIM_HIZ)
LDO_3V3: R67.2 R68.2 R69.2 R70.2 ; port LDO_3V3
LODRV1: R43.1 U7.25(LODRV1)
LODRV2: R44.1 U7.21(LODRV2)
MODE: R61.2 U7.17(MODE)
P_OUT: C51.2(ANODE) C52.2 C53.1 C54.1 C62.1(+) Q4.5-6-7-8(D) R33.1 R35.1
PPHV: C31.2 C44.2 C45.1 C55.2(ANODE) C56.1 C57.1(+) C59.1 R30.1 R31.2 R45.2 R54.1 U7.33(VAC) ; port PPHV
REGN: C46.1 R38.2 R53.1 U7.24(REGN)
SRN: C30.2 C35.1 R36.2 U7.13(SRN)
SRP: C30.1 C34.1 R35.2 U7.14(SRP)
STAT1: R69.1 U7.4(STAT1)
STAT2: R70.1 U7.5(STAT2)
SW1: C40.1 L2.1 Q5.1(S) Q5.2(S) Q5.3(S) Q7.5-6-7-8(D) R41.2 U7.28(SW1)
SW2: C41.2 L2.2 Q4.1(S) Q4.2(S) Q4.3(S) Q6.5-6-7-8(D) R42.2 U7.18(SW2)
TS: R38.1 R39.2 R40.2 U7.8(TS)
VBUS: R56.1 ; port VBUS
VSYS: C47.2 C48.2(ANODE) C49.1 C50.1 Q5.5-6-7-8(D) R30.2 R32.2
I2Cc_SCL: R64.2 ; port I2Cc_SCL
I2Cc_SDA: R63.2 ; port I2Cc_SDA
PP7V: R55.1 ; port PP7V
NetC6_2: C6.2 R54.2 R56.2 U7.32(VAC)
NetC36_1: C36.1 R41.1
NetC37_1: C37.1 R42.1
NetC40_2: C40.2 D3.1(CATHODE) R49.2
NetC41_1: C41.1 D4.1(CATHODE) R50.2
NetC42_1: C42.1 R51.1
NetJP1_1: JP1.1 R58.2
NetJP1_3: JP1.3 R59.2
NetQ4_4: Q4.4(G) R34.1
NetQ5_4: Q5.4(G) R37.1
NetQ6_4: Q6.4(G) R44.2
NetQ7_4: Q7.4(G) R43.2
NetR63_1: R63.1 U7.2(SDA)
NetR64_1: R64.1 U7.1(SCL)

Not connected (* = marked no-connect by the designer): U7 15(NC)* 16(NC)* 31(NC)*

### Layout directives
net class HV: ACN, ACP, ACUV, HIDRV1, NetC36_1, NetC40_2, NetQ5_4, SW1, VSYS
net class HHV: BAT, HIDRV2, NetC37_1, NetC41_1, NetQ4_4, P_OUT, SRN, SRP, SW2
net class LV: GND, LODRV1, LODRV2

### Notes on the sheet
- 48V DC Input
- (near R30) 2m default, higher Resister for better regulation
- (near R33) 5m is fixed, do not change
- VOUT/VBAT 6S-14S 18V to 56V
- To BATTERY PACK
- (near L2) L: 10uH DCR: 1.75m-60m
- JEITA compliance
- Use Kelvin sense for ACP/ACN
- Use Kelvin sense for SRP/SRN
- DNP
- (near R42) DNP
- (near C38) ACUV=1.1V
- (near C36) DNP
- *snubber circuit as placeholders only
- 10K R1 is just for emulating normal temp condition
- (near R46) UV-3.75V  Vindpm=4.1V, OV-SET to 55V
- BAT Voltage Selection Table
- VBAT
- (near C39) ACOV=1.2V
- R52 for ACOV setting
- JP_A
- Default
- 7S(29.4V)
- 10S(42V)
- JP_B
- 14S(58.8V)
- (near R53) DNP
- Suggest to use 7V
- (near R56) DNP
- VFB=1.536V
- (near JP1) A
- (near JP1) B
- (near R57) Default: 7S(29.4V)
- (near R58) 10S (42V)
- 1,FBG Pin internal to ground 12R resistor
  2, turn off feedback network to minimize feedback resistor loss when not working
- Set Input Current Limit throuhg ILIM_HIZ pin or Register, the lower will win
- ILIM=KLIM/RLIM=20/3.6=5.5A
- KLIM=50A*Kohm for 2m Input Current Sense
- KLIM=20A*Kohm for 5m Input Current Sense
- Set Charge current throuhg ICHG pin or Register, the lower will win
- KICHG=50A*Kohm
- ICHG=KICHG/RCHG=6A

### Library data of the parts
C6 C44 = CMP-0081011-1: CAP, CERM, 0.1 µF, 100 V,+/- 10%, X7R, AEC-Q200 Grade 1, 0603; Manufacturer: Taiyo Yuden; SizeAreaWB_mm2: 4.68; SizeArea_mm2: 1.28; AEC Qualified: Y; AEC Category: Q200; Value: 0.1uF; TaMax_C: 125°C; SizeZ_mm: 1; Polarized: N; TaMin_C: -55°C; VDC_V: 100V; SizeY_mm: 0.8; U/M: EA; SizeX_mm: 1.6; Cap_Case: 0603; ValueDisplayed: 0.1µF
C29 C30 = CMP-0006944-4: CAP, CERM, 0.47 uF, 16 V, +/- 10%, X7R, 0603; Manufacturer: Kemet; TaMin_C: -55°C; Polarized: N; SizeAreaWB_mm2: 4.68; Value1: Unknown; U/M: EA; Value: 0.47uF; TaMax_C: 125°C; SizeZ_mm: 1; SizeX_mm: 1.6; SizeY_mm: 0.8; SizeArea_mm2: 1.28; AEC Category: Q200
C31 C56 = CMP-0093675-1: 4.7uF ±10% 100V Ceramic Capacitor X7S 1210 (3225 Metric); Manufacturer: Murata; Value: 4.7µF; AEC Qualified: Yes; TempCo: 22%; SizeZ_mm: 2.3mm; AEC Grade: Grade 1
C32-C35 C38 C39 C50 = CMP-0081011-1: CAP, CERM, 0.1 µF, 100 V,+/- 10%, X7R, AEC-Q200 Grade 1, 0603; Manufacturer: Taiyo Yuden; SizeAreaWB_mm2: 4.68; SizeArea_mm2: 1.28; AEC Qualified: Y; AEC Category: Q200; Value: 0.1uF; TaMax_C: 125°C; SizeZ_mm: 1; Polarized: N; TaMin_C: -55°C; SizeY_mm: 0.8; U/M: EA; SizeX_mm: 1.6; Cap_Case: 0603; ValueDisplayed: 0.1µF
C36 C37 = CMP-0006722-4: CAP, CERM, 33 pF, 100 V, +/- 5%, C0G/NP0, 0603; Manufacturer: AVX; TaMin_C: -55°C; ESR_ohm: 0.209; Polarized: N; SizeAreaWB_mm2: 4.68; Value1: 0.209 ohm; U/M: EA; Value: 33pF; TaMax_C: 125°C; SizeZ_mm: 1; SizeX_mm: 1.6; SizeY_mm: 0.8; Cap_Case: 0603; SizeArea_mm2: 1.28; AEC Category: Q200
C40 C41 = CMP-0006753-4: CAP, CERM, 0.1 uF, 25 V, +/- 10%, X7R, 0603; Manufacturer: AVX; TaMin_C: -55°C; ESR_ohm: 50m; Polarized: N; SizeAreaWB_mm2: 4.68; Value1: 0.05 ohm; U/M: EA; Value: 0.1uF; TaMax_C: 125°C; SizeZ_mm: 1; SizeX_mm: 1.6; SizeY_mm: 0.8; Cap_Case: 0603; SizeArea_mm2: 1.28; AEC Category: Q200
C42 = CMP-0007130-4: CAP, CERM, 100 pF, 100 V, +/- 5%, C0G/NP0, AEC-Q200 Grade 1, 0603; Manufacturer: MuRata; TaMin_C: -55°C; Polarized: N; SizeAreaWB_mm2: 4.68; Value1: Unknown; U/M: EA; TaMax_C: 125°C; SizeZ_mm: 1; SizeX_mm: 1.6; SizeY_mm: 0.8; Cap_Case: 0603; SizeArea_mm2: 1.28; AEC Qualified: Y; AEC Category: Q200; Value: 100pF
C43 C46 = CMP-0093626-1: Cap Ceramic 4.7uF 25V X7R 10% Pad SMD 0805 +125°C Automotive T/R; Manufacturer: TDK Corporation; SizeZ_mm: 1.45mm; TempCo: 15%; AEC Qualified: Yes; Value: 4.7µF; Tolerance_%: 0.1%; AEC Grade: Grade 1
C45 C49 C53 C59 C64 = CMP-0861070-1: CAP, CERM, 1 µF, 100 V,+/- 10%, X7R, AEC-Q200 Grade 1, 0805; Manufacturer: AVX; SizeZ_mm: 1.5; Polarized: N; TaMax_C: 125°C; TaMin_C: -55°C; Value: 1uF; AEC Qualified: Y; U/M: EA; AEC Grade: 1; Cap_Case: 0805; SizeX_mm: 2; SizeArea_mm2: 2.5; SizeAreaWB_mm2: 6.75; AEC Category: Q200; SizeY_mm: 1.25
C47 C52 = CMP-0096021-1: 10 µF ±10% 100V Ceramic Capacitor X7R 1210 (3225 Metric); Manufacturer: TDK; Cap_F: 10µF; AEC Qualified: No; Value: 10µF; SizeZ_mm: 2.85mm; TempCo: 15%
C48 C51 C55 C60 = CMP-0089206-1: 100uF 63V Polymer ALUM Electrolytic Capacitor, CR Series 4000h 10.3x10.3x12.6mm; Manufacturer: Nichicon; Tolerance_%: 20%; AEC Grade: Grade 1; Cap_F: 100µF; IRMS_A: 3A; Life: 4000Hours; AEC Qualified: Yes; SizeZ_mm: 12.7mm; Dissipation Factor: 8%; Esr: 24m; Leakage Current: 189uA
C54 = CMP-0007237-3: Multilayer Ceramic Capacitors MLCC - SMD/SMT CGA 0603 100V 100pF C0G 5% AEC-Q200; Manufacturer: TDK; TaMin_C: -55°C; Polarized: N; TempCo: C0G/NP0; SizeAreaWB_mm2: 4.68; Value1: Unknown; U/M: EA; TaMax_C: 125°C; SizeZ_mm: 1; SizeX_mm: 1.6; SizeY_mm: 0.8; SizeArea_mm2: 1.28; AEC Category: Q200
C57 C62 = CMP-0012603-3: CAP, Polymer Hybrid, 56 uF, 63 V, +/- 20%, 30 ohm, 10x10 SMD; Manufacturer: Panasonic; TaMin_C: -55°C; ESR_ohm: 30; Polarized: Y; SizeAreaWB_mm2: 159.9; Value1: 30 ohm; Value: 56uF; TaMax_C: 125°C; SizeZ_mm: 10.2; SizeX_mm: 11; SizeY_mm: 10.3; SizeArea_mm2: 113.3; CompType: Capacitor; Cap_F: 56µF; IRMS_A: 1.4A; AEC Category: Q200
D3 D4 = CMP-0093639-2: Diode Schottky 1A Surface Mount DO-219AB (SMF); Manufacturer: Vishay; Max Surge Forward Current: 30A; TJmax_C: 175°C; AEC Qualified: No; Cap_F: 95pF; AEC Category: Q101; Standoff Height: 0mm; SizeZ_mm: 1.08mm; Vr_V: 100V; Peak Reverse Current: 0.2uA
JP1 = CMP-0002338-1: Header, 100mil, 3x1, Tin, TH; Manufacturer: Sullins Connector Solutions; Cert_UL: Y; CNHeader: TRUE; CT: FALSE; Current_A: 3A; Gender: Male; Green_Lifecycle: Not Set; Green_REACh: Incomplete; Pitch_mm: 2.54; Row_Count: 1; Shrouded: N; Voltage_V: 1.8kV
L2 = CMP-0096007-1: Power Choke Coil 10uH 20% 9A 22mOhm; Manufacturer: Cyntec; Material: Metal Dust; SizeZ_mm: 5mm; Standoff Height: 0mm; Ind_H: 10µH; AEC Qualified: No; Isat: 10.5A; Test Frequency: 100kHz; DCR_ohm: 22m
Q4-Q7 = CMP-0096839-1: N-Channel 80 V 18.6A (Ta), 70.6A (Tc) 5W (Ta), 71.4W (Tc) Surface Mount PowerPAK® SO-8; Manufacturer: Vishay; QgTyp_nC: 43.5nC @ 10V; Turn On Delay Time: 12ns; Rthja Max: 20°C/W; Turn Off Delay Time: 40ns; Reverse Recovery Charge: 52nC; Typ Forward Diode Voltage: 0.74V; VdsMax_V: 1.1V; SizeZ_mm: 1.12mm; Number Of Channels: 1; Pulse Drain Current: 200A; Threshold Vgs Min: 1V; TJmax_C: +150°C; AEC Qualified: No; Transconductance: 49S; ChMode: False; Reverse Recovery Time: 38ns; Threshold Vgs Max: 2.4V; Input Capacitace At Vds: 2930pF @ 40V; Vgs_V: 20V; Drain To Source Breakdown Voltage: 80V; Rdson45_ohm: 5.3m
R30 R33 = CMP-0096841-1: Res Metal Strip 2512 0.005 Ohm 1% 1W 110ppm/C Molded SMD SMD Embossed Plastic T/R; Manufacturer: Vishay; TempCo: 110ppm/°C; AEC Grade: Grade 0; AEC Qualified: Yes; Category 5A00970A6D5C81C7: Uncategorized; Value: 5m; Category 5C6A91606D4187Ad: Resistors; Category Cd01000Bfc2916C6: Single Components; Category 7542B8484461Ae85: Passive Components; SizeZ_mm: 0.889mm
R31 R32 R35 R36 = CMP-0093685-1: RES Thick Film, 10Ω, 1%, 0.1W, 100ppm/°C, 0603; Manufacturer: Vishay; Approved Alternate Part Number: 541-1.00HHCT-ND; Power_W: 100mW; Voltage: 75V; SizeZ_mm: 0.5mm; AEC Grade: Grade 0; AEC Qualified: Yes
R34 R37 R43 R44 R49 R50 R53-R56 = CMP-0093629-1: Thick Film Resistors - SMD 1/10watt ZEROohm Jumper; Manufacturer: Vishay; AEC Grade: Grade 0; TempCo: 100ppm/°C; Power: 250mW; Res_ohm: 1.5; Power_W: 330mW; AEC Qualified: Yes; VDC_V: 75V; SizeZ_mm: 0.55mm; Tolerance_%: 1%
R38 = CMP-0023199-5: RES, 5.23 k, 1%, 0.1 W, 0603; Manufacturer: Yageo; Power_W: 100mW; TempCo: 100 ppm/C; Value_Code: 5k23; Value: 5.23k; EIA_Code: E96; SizeX_mm: 1.6; SizeY_mm: 0.8; SizeZ_mm: 1; Value2: 0.1W; SizeArea_mm2: 1.28; AEC Qualified: N; VDC_V: 75V; AEC Category: Q200; SizeAreaWB_mm2: 4.68
R39 = CMP-0022684-2: RES, 10.0 k, 1%, 0.1 W, 0603; Manufacturer: Panasonic; Power_W: 100mW; TempCo: 100 ppm/C; Value_Code: 10k0; U/M: EA; Value: 10.0k; EIA_Code: E96; Res_ohm: 10k; SizeX_mm: 1.6; SizeY_mm: 0.8; SizeZ_mm: 1; Value2: 0.1W; SizeArea_mm2: 1.28; VDC_V: 75V; AEC Category: Q200
R40 = CMP-0023018-5: RES, 30.1 k, 1%, 0.1 W, 0603; Manufacturer: Yageo; Power_W: 100mW; TempCo: 100 ppm/C; Value_Code: 30k1; Value: 30.1k; EIA_Code: E96; SizeX_mm: 1.6; SizeY_mm: 0.8; SizeZ_mm: 1; Value2: 0.1W; SizeArea_mm2: 1.28; AEC Qualified: N; VDC_V: 75V; AEC Category: Q200; SizeAreaWB_mm2: 4.68
R41 R42 = CMP-0020812-2: RES, 2.2, 5%, 0.125 W, 0805; Manufacturer: Yageo America; Power_W: 125mW; TempCo: 200 ppm/C; Value_Code: 2R20; U/M: EA; Value: 2.2; EIA_Code: E24; SizeX_mm: 2; SizeY_mm: 1.25; SizeZ_mm: 1.45; Value2: 0.125W; SizeArea_mm2: 2.5; VDC_V: 150V; AEC Category: Q200
R45 = CMP-0021522-3: Thick Film Resistors - SMD 1/8Watt 1Mohms 1% Commercial Use; Manufacturer: Vishay / Dale; Power_W: 125mW; TempCo: 100 ppm/C; Value_Code: 1M00; Value: 1.00Meg; EIA_Code: E96; Res_ohm: 1M; SizeX_mm: 2; SizeY_mm: 1.25; SizeZ_mm: 1.45; Value2: 0.125W; SizeArea_mm2: 2.5; AEC Qualified: Y; AEC Category: Q200; AEC Grade: 0; SizeAreaWB_mm2: 6.75
R46 = CMP-0024170-1: RES, 383 k, 0.1%, 0.1 W, 0603; Manufacturer: Yageo America; Power_W: 100mW; TempCo: 25 ppm/C; U/M: EA; Value: 383k; EIA_Code: E192; SizeX_mm: 1.6; SizeY_mm: 0.8; SizeZ_mm: 1; Value2: 0.1W; SizeArea_mm2: 1.28; VDC_V: 75V; AEC Category: Q200
R47 = CMP-0024106-3: RES, 31.2 k, 0.1%, 0.1 W, 0603; Manufacturer: Yageo America; Power_W: 100mW; TempCo: 25 ppm/C; Value_Code: 31k2; U/M: EA; Value: 31.2k; EIA_Code: E192; SizeX_mm: 1.6; SizeY_mm: 0.8; SizeZ_mm: 1; Value2: 0.1W; SizeArea_mm2: 1.28; VDC_V: 75V; AEC Category: Q200
R51 = CMP-0025744-3: RES, 1.1, 5%, 0.1 W, 0603; Manufacturer: Vishay-Dale; Power_W: 100mW; TempCo: 200 ppm/C; Value_Code: 1R10; U/M: EA; Value: 1.1; EIA_Code: E24; SizeX_mm: 1.6; SizeY_mm: 0.8; SizeZ_mm: 1; Value2: 0.1W; SizeArea_mm2: 1.28; VDC_V: 75V; AEC Category: Q200
R52 = CMP-0018933-2: Thick Film Resistors - SMD 0805 Anti-Surge Res. 0.1%, 249Kohm; Manufacturer: Panasonic; Power_W: 125mW; TempCo: 25 ppm/C; U/M: EA; Value: 249k; EIA_Code: E192; SizeX_mm: 2; SizeY_mm: 1.25; SizeZ_mm: 1.45; Value2: 0.125W; SizeArea_mm2: 2.5; VDC_V: 100V; AEC Category: Q200
R57 = CMP-0023733-2: RES, 13.7 k, 0.1%, 0.1 W, 0603; Manufacturer: Yageo America; Power_W: 100mW; TempCo: 25 ppm/C; Value_Code: 13k7; U/M: EA; Value: 13.7k; EIA_Code: E192; SizeX_mm: 1.6; SizeY_mm: 0.8; SizeZ_mm: 1; Value2: 0.1W; SizeArea_mm2: 1.28; VDC_V: 75V; AEC Category: Q200
R58 = CMP-0024097-2: RES, 30.5 k, 0.1%, 0.1 W, 0603; Manufacturer: Yageo America; Power_W: 100mW; TempCo: 25 ppm/C; Value_Code: 30k5; U/M: EA; Value: 30.5k; EIA_Code: E192; SizeX_mm: 1.6; SizeY_mm: 0.8; SizeZ_mm: 1; Value2: 0.1W; SizeArea_mm2: 1.28; VDC_V: 75V; AEC Category: Q200
R59 = CMP-0023735-1: RES, 13.0 k, 0.1%, 0.1 W, 0603; Manufacturer: Yageo America; Power_W: 100mW; TempCo: 25 ppm/C; Value_Code: 13k0; U/M: EA; Value: 13.0k; EIA_Code: E192; Res_ohm: 13k; SizeX_mm: 1.6; SizeY_mm: 0.8; SizeZ_mm: 1; Value2: 0.1W; SizeArea_mm2: 1.28; VDC_V: 75V; AEC Category: Q200
R61 = CMP-0022371-2: RES, 3.01 k, 1%, 0.1 W, 0603; Manufacturer: Vishay-Dale; Power_W: 100mW; TempCo: 100 ppm/C; Value_Code: 3k01; U/M: EA; Value: 3.01k; EIA_Code: E96; SizeX_mm: 1.6; SizeY_mm: 0.8; SizeZ_mm: 1; Value2: 0.1W; SizeArea_mm2: 1.28; VDC_V: 75V; AEC Category: Q200
R62 = CMP-0022735-5: as R14 on sheet 2_PD Control TPS26750
R63 R64 = CMP-0092857-1: Thick Film Resistors - SMD 1/8watt ZEROohm Jumper; Manufacturer: Vishay; Power_W: 500mW; SizeZ_mm: 0.6mm; AEC Qualified: Yes; TempCo: 200ppm/°C; VDC_V: 150V; Tolerance_%: 5%; AEC Grade: Grade 0
R65 = CMP-0023086-5: RES, 3.60 k, 1%, 0.1 W, 0603; Manufacturer: Yageo; Power_W: 100mW; TempCo: 100 ppm/C; Value_Code: 3k60; Value: 3.60k; Res_ohm: 3.6k; SizeX_mm: 1.6; SizeY_mm: 0.8; SizeZ_mm: 1; Value2: 0.1W; SizeArea_mm2: 1.28; AEC Qualified: N; VDC_V: 75V; AEC Category: Q200; SizeAreaWB_mm2: 4.68
R67-R70 = CMP-0078781-1: RES, 10.5 k, 1%, 0.063 W, 0402; Manufacturer: Yageo America; Value_Code: 10k5; SizeArea_mm2: 0.5; AEC Qualified: N; AEC Category: Q200; Value: 10.5k; SizeZ_mm: 0.6; EIA_Code: E96; TempCo: 100 ppm/C; Power_W: 63mW; VDC_V: 50V; Value2: 0.063W; SizeX_mm: 1
R71 = CMP-0023607-3: RES, 8.20 k, 0.1%, 0.1 W, 0603; Manufacturer: Susumu Co Ltd; Power_W: 100mW; TempCo: 25 ppm/C; Value_Code: 8k20; U/M: EA; Value: 8.20k; Res_ohm: 8.2k; SizeX_mm: 1.6; SizeY_mm: 0.8; SizeZ_mm: 1; Value2: 0.1W; SizeArea_mm2: 1.28; VDC_V: 75V; AEC Category: Q200
U7 = CMP-0093460-1: Manufacturer: Texas Instruments; Alternate Manufacturer: None; AEC Qualified: No; Standoff Height: 0mm; SizeZ_mm: 1mm

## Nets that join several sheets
BAT: 4_PP5V Bias (R23.2), 3_BQ25756 Charger (6 pins)
GND: 2_PD Control TPS26750 (49 pins), 4_PP5V Bias (14 pins), 3_BQ25756 Charger (45 pins)
LDO_3V3: 2_PD Control TPS26750 (21 pins), 3_BQ25756 Charger (R67.2 R68.2 R69.2 R70.2)
PPHV: 2_PD Control TPS26750 (J2.1), 3_BQ25756 Charger (12 pins)
VBUS: 2_PD Control TPS26750 (10 pins), 3_BQ25756 Charger (R56.1)
VIN_3V3: 2_PD Control TPS26750 (C18.1 U1.32), 4_PP5V Bias (R26.1)
I2Cc_SCL: 2_PD Control TPS26750 (R6.1 R109.2 U1.16 U3.6), 3_BQ25756 Charger (R64.2)
I2Cc_SDA: 2_PD Control TPS26750 (5 pins), 3_BQ25756 Charger (R63.2)
PP5V: 2_PD Control TPS26750 (C13.1 C14.1 U1.28 U1.29), 4_PP5V Bias (C20.1 U4.5)
PP7V: 4_PP5V Bias (7 pins), 3_BQ25756 Charger (R55.1)

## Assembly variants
001: not fitted R17 R19 R41 R42 R53 R56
